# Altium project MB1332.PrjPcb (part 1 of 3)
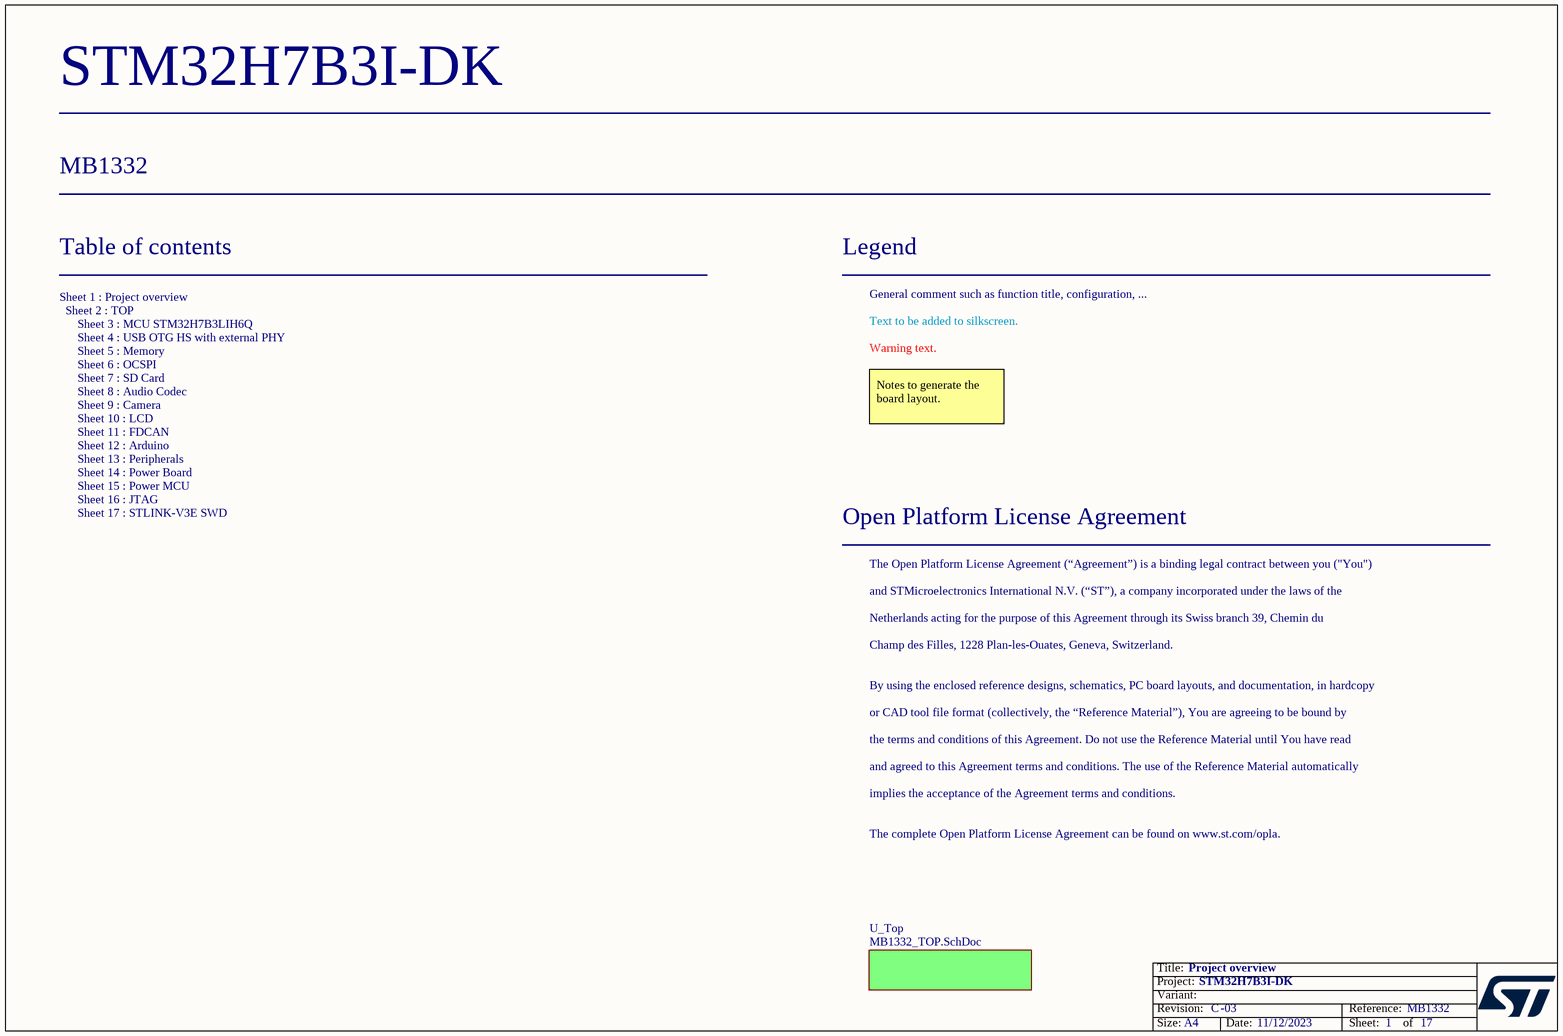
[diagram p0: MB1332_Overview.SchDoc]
Board_Assembly_Revision: 03; Board_Document_Date: 11/12/2023; Board_Name: STM32H7B3I-DK; Board_PCB_Revision: C; Board_Reference: MB1332
17 sheets, 382 parts. Net scope: flat (ports and power ports of the same name join across sheets).
Board file: MB1332.PcbDoc
Sheets:
  MB1332_Overview.SchDoc
    U_Top = MB1332_TOP.SchDoc
      U_Audio_Codec = Audio_Codec.SchDoc
      U_Camera = Camera.SchDoc
      U_FDCAN = FDCAN.SchDoc
      U_LCD = LCD.SchDoc
      U_Memory = Memory.SchDoc
      U_OCSPI = OCSPI.SchDoc
      U_Peripherals = Peripherals.SchDoc
      U_SDcard = SDcard.SchDoc
      U_USB_OTG_HS_externalPHY = USB_OTG_HS_externalPHY.SchDoc
      U_MCU = MCU.SchDoc
      U_Arduino = Arduino.SchDoc
      U_JTAG = JTAG.SchDoc
      U_STLink_V3E_SWD = STLink_V3E_SWD.SchDoc
      U_Power_Board = Power_Board.SchDoc
      U_Power_MCU = Power_MCU.SchDoc

## Sheet MB1332_Overview.SchDoc: Project overview
size A4; Date: Not used; ApprovedBy: Not used; CheckedBy: Not used; Author: Not used; CompanyName: STMicroelectronics; DrawnBy: Not used; Engineer: Not used; Organization: Not used; Address1: Not used; Address2: Not used; Address3: Not used; Address4: Not used; DocumentNumber: Not used; Revision: Not used; SheetNumber: 1; SheetTotal: 17

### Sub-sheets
U_Top = MB1332_TOP.SchDoc: no entries

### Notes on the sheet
- Table of contents
- Legend
- General comment such as function title, configuration, ...
- Text to be added to silkscreen.
- Warning text.
- Notes to generate the board layout.
- Sheet 1 : Project overview
  Sheet 2 : TOP
  Sheet 3 : MCU STM32H7B3LIH6Q
  Sheet 4 : USB OTG HS with external PHY
  Sheet 5 : Memory
  Sheet 6 : OCSPI
  Sheet 7 : SD Card
  Sheet 8 : Audio Codec
  Sheet 9 : Camera
  Sheet 10 : LCD
  Sheet 11 : FDCAN
  Sheet 12 : Arduino
  Sheet 13 : Peripherals
  Sheet 14 : Power Board
  Sheet 15 : Power MCU
  Sheet 16 : JTAG
  Sheet 17 : STLINK-V3E SWD
- Open Platform License Agreement
- The Open Platform License Agreement (“Agreement”) is a binding legal contract between you ("You")
- and STMicroelectronics International N.V. (“ST”), a company incorporated under the laws of the
- Netherlands acting for the purpose of this Agreement through its Swiss branch 39, Chemin du
- Champ des Filles, 1228 Plan-les-Ouates, Geneva, Switzerland.
- By using the enclosed reference designs, schematics, PC board layouts, and documentation, in hardcopy
- or CAD tool file format (collectively, the “Reference Material”), You are agreeing to be bound by
- the terms and conditions of this Agreement. Do not use the Reference Material until You have read
- and agreed to this Agreement terms and conditions. The use of the Reference Material automatically
- implies the acceptance of the Agreement terms and conditions.
- The complete Open Platform License Agreement can be found on www.st.com/opla.

## Sheet MB1332_TOP.SchDoc: TOP
size A3; Date: Not used; ApprovedBy: Not used; CheckedBy: Not used; Author: Not used; CompanyName: STMicroelectronics; DrawnBy: Not used; Engineer: Not used; Organization: Not used; Address1: Not used; Address2: Not used; Address3: Not used; Address4: Not used; DocumentNumber: Not used; Revision: Not used; SheetNumber: 2; SheetTotal: 17
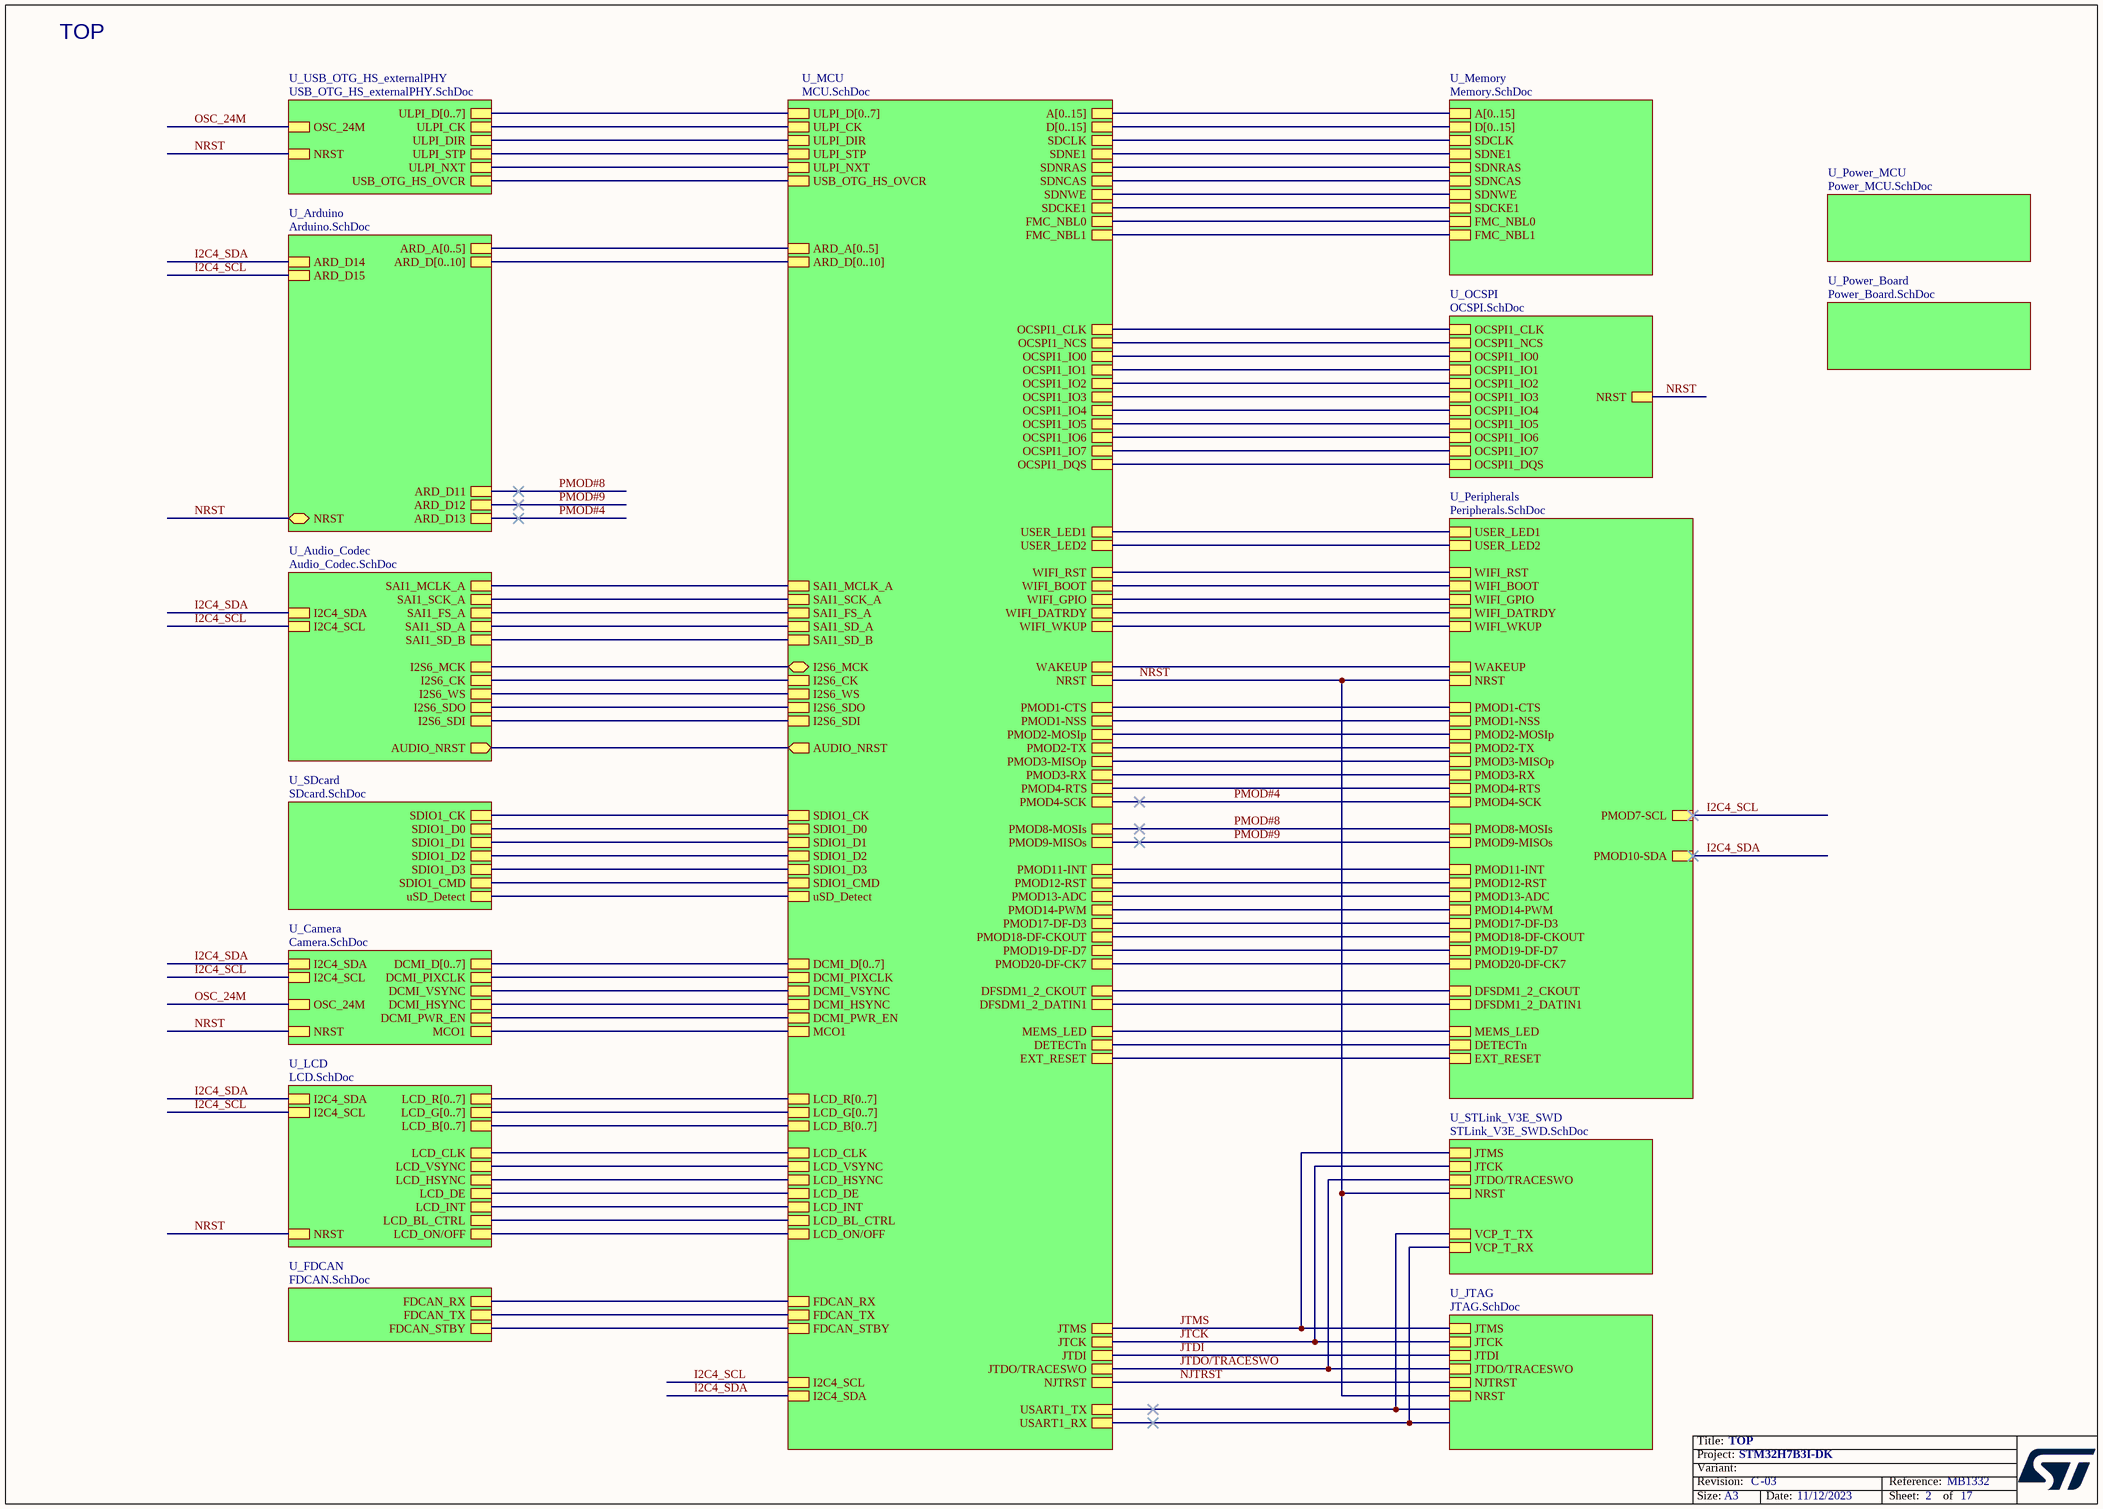
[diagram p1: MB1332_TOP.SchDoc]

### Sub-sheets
U_Arduino = Arduino.SchDoc: ARD_D13, ARD_D12, ARD_D11, ARD_D15, ARD_D14, ARD_A[0..5], ARD_D[0..10], NRST (bidir)
U_Audio_Codec = Audio_Codec.SchDoc: SAI1_MCLK_A, SAI1_SCK_A, SAI1_FS_A, SAI1_SD_A, SAI1_SD_B, I2C4_SCL, I2C4_SDA, I2S6_MCK, I2S6_CK, I2S6_WS, I2S6_SDO, I2S6_SDI, AUDIO_NRST (out)
U_Camera = Camera.SchDoc: NRST, DCMI_D[0..7], DCMI_PWR_EN, DCMI_VSYNC, DCMI_PIXCLK, I2C4_SDA, I2C4_SCL, DCMI_HSYNC, MCO1, OSC_24M
U_FDCAN = FDCAN.SchDoc: FDCAN_STBY, FDCAN_RX, FDCAN_TX
U_JTAG = JTAG.SchDoc: JTMS, JTCK, JTDI, JTDO/TRACESWO, NJTRST, NRST
U_LCD = LCD.SchDoc: LCD_R[0..7], I2C4_SDA, I2C4_SCL, LCD_B[0..7], LCD_G[0..7], NRST, LCD_HSYNC, LCD_VSYNC, LCD_CLK, LCD_DE, LCD_INT, LCD_BL_CTRL, LCD_ON/OFF
U_MCU = MCU.SchDoc: OCSPI1_NCS, SAI1_MCLK_A, SDNCAS, SDNE1, SDCKE1, NRST, LCD_HSYNC, LCD_VSYNC, LCD_CLK, MCO1, OCSPI1_CLK, OCSPI1_DQS, SDIO1_D0, SDIO1_D1, SDIO1_D2, SDIO1_D3, SDIO1_CK, WAKEUP, SDIO1_CMD, FMC_NBL0, FMC_NBL1, SDNRAS, LCD_G[0..7], LCD_B[0..7], D[0..15], A[0..15], ULPI_D[0..7], LCD_R[0..7], LCD_DE, ULPI_STP, ULPI_CK, LCD_INT, uSD_Detect, LCD_BL_CTRL, SAI1_SD_B, SAI1_FS_A, SAI1_SCK_A, SAI1_SD_A, JTMS, JTCK, JTDI, JTDO/TRACESWO, NJTRST, DCMI_HSYNC, DCMI_D[0..7], DCMI_PIXCLK, OCSPI1_IO1, OCSPI1_IO2, OCSPI1_IO3, OCSPI1_IO4, OCSPI1_IO7, OCSPI1_IO6, OCSPI1_IO5, ULPI_DIR, ULPI_NXT, SDNWE, DCMI_VSYNC, DCMI_PWR_EN, I2C4_SDA, I2C4_SCL, I2S6_SDO, I2S6_SDI, I2S6_CK, SDCLK, USB_OTG_HS_OVCR, USART1_TX, USART1_RX, OCSPI1_IO0, LCD_ON/OFF, FDCAN_RX, FDCAN_TX, FDCAN_STBY, MEMS_LED, EXT_RESET, DFSDM1_2_CKOUT, DFSDM1_2_DATIN1, I2S6_WS, WIFI_RST, ARD_A[0..5], ARD_D[0..10], USER_LED2, USER_LED1, AUDIO_NRST (out), PMOD13-ADC, PMOD12-RST, PMOD4-SCK, PMOD20-DF-CK7, PMOD8-MOSIs, PMOD2-MOSIp, PMOD3-RX, PMOD1-NSS, PMOD1-CTS, PMOD2-TX, PMOD11-INT, PMOD4-RTS, PMOD14-PWM, PMOD18-DF-CKOUT, PMOD9-MISOs, PMOD17-DF-D3, PMOD19-DF-D7, PMOD3-MISOp, WIFI_BOOT, I2S6_MCK (bidir), WIFI_WKUP, WIFI_GPIO, WIFI_DATRDY, DETECTn
U_Memory = Memory.SchDoc: FMC_NBL0, FMC_NBL1, D[0..15], A[0..15], SDNCAS, SDNWE, SDNRAS, SDNE1, SDCKE1, SDCLK
U_OCSPI = OCSPI.SchDoc: NRST, OCSPI1_IO0, OCSPI1_IO1, OCSPI1_IO2, OCSPI1_IO3, OCSPI1_IO4, OCSPI1_IO5, OCSPI1_IO6, OCSPI1_IO7, OCSPI1_DQS, OCSPI1_CLK, OCSPI1_NCS
U_Peripherals = Peripherals.SchDoc: WIFI_RST, WAKEUP, NRST, DFSDM1_2_CKOUT, DFSDM1_2_DATIN1, MEMS_LED, EXT_RESET, USER_LED2, USER_LED1, PMOD4-RTS, PMOD2-MOSIp, PMOD3-MISOp, PMOD1-CTS, PMOD2-TX, PMOD8-MOSIs, PMOD9-MISOs, PMOD3-RX, PMOD4-SCK, PMOD7-SCL, PMOD10-SDA, PMOD11-INT, PMOD12-RST, PMOD17-DF-D3, PMOD18-DF-CKOUT, PMOD19-DF-D7, PMOD13-ADC, PMOD14-PWM, PMOD20-DF-CK7, PMOD1-NSS, WIFI_BOOT, WIFI_WKUP, WIFI_GPIO, WIFI_DATRDY, DETECTn
U_Power_Board = Power_Board.SchDoc: no entries
U_Power_MCU = Power_MCU.SchDoc: no entries
U_SDcard = SDcard.SchDoc: SDIO1_D0, SDIO1_D1, SDIO1_D2, SDIO1_D3, SDIO1_CMD, SDIO1_CK, uSD_Detect
U_STLink_V3E_SWD = STLink_V3E_SWD.SchDoc: JTCK, JTDO/TRACESWO, NRST, JTMS, VCP_T_TX, VCP_T_RX
U_USB_OTG_HS_externalPHY = USB_OTG_HS_externalPHY.SchDoc: ULPI_D[0..7], ULPI_CK, ULPI_DIR, ULPI_NXT, ULPI_STP, NRST, USB_OTG_HS_OVCR, OSC_24M

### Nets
I2C4_SCL: sheet U_Audio_Codec/I2C4_SCL, sheet U_Camera/I2C4_SCL, sheet U_LCD/I2C4_SCL, sheet U_Peripherals/PMOD7-SCL, sheet U_MCU/I2C4_SCL, sheet U_Arduino/ARD_D15
I2C4_SDA: sheet U_Audio_Codec/I2C4_SDA, sheet U_Camera/I2C4_SDA, sheet U_LCD/I2C4_SDA, sheet U_Peripherals/PMOD10-SDA, sheet U_MCU/I2C4_SDA, sheet U_Arduino/ARD_D14
JTCK: sheet U_MCU/JTCK, sheet U_JTAG/JTCK, sheet U_STLink_V3E_SWD/JTCK
JTDI: sheet U_MCU/JTDI, sheet U_JTAG/JTDI
JTDO/TRACESWO: sheet U_MCU/JTDO/TRACESWO, sheet U_JTAG/JTDO/TRACESWO, sheet U_STLink_V3E_SWD/JTDO/TRACESWO
JTMS: sheet U_MCU/JTMS, sheet U_JTAG/JTMS, sheet U_STLink_V3E_SWD/JTMS
NJTRST: sheet U_MCU/NJTRST, sheet U_JTAG/NJTRST
NRST: sheet U_Camera/NRST, sheet U_LCD/NRST, sheet U_OCSPI/NRST, sheet U_Peripherals/NRST, sheet U_USB_OTG_HS_externalPHY/NRST, sheet U_MCU/NRST, sheet U_Arduino/NRST, sheet U_JTAG/NRST, sheet U_STLink_V3E_SWD/NRST
OSC_24M: sheet U_Camera/OSC_24M, sheet U_USB_OTG_HS_externalPHY/OSC_24M
PMOD#4: sheet U_Peripherals/PMOD4-SCK, sheet U_MCU/PMOD4-SCK, sheet U_Arduino/ARD_D13
PMOD#8: sheet U_Peripherals/PMOD8-MOSIs, sheet U_MCU/PMOD8-MOSIs, sheet U_Arduino/ARD_D11
PMOD#9: sheet U_Peripherals/PMOD9-MISOs, sheet U_MCU/PMOD9-MISOs, sheet U_Arduino/ARD_D12
(unnamed): sheet U_Audio_Codec/SAI1_MCLK_A, sheet U_MCU/SAI1_MCLK_A
(unnamed): sheet U_Audio_Codec/SAI1_SCK_A, sheet U_MCU/SAI1_SCK_A  [a separate net that carries the same name]
(unnamed): sheet U_Audio_Codec/SAI1_FS_A, sheet U_MCU/SAI1_FS_A  [a separate net that carries the same name]
(unnamed): sheet U_Audio_Codec/SAI1_SD_A, sheet U_MCU/SAI1_SD_A  [a separate net that carries the same name]
(unnamed): sheet U_Audio_Codec/SAI1_SD_B, sheet U_MCU/SAI1_SD_B  [a separate net that carries the same name]
(unnamed): sheet U_Audio_Codec/I2S6_MCK, sheet U_MCU/I2S6_MCK  [a separate net that carries the same name]
(unnamed): sheet U_Audio_Codec/I2S6_CK, sheet U_MCU/I2S6_CK  [a separate net that carries the same name]
(unnamed): sheet U_Audio_Codec/I2S6_WS, sheet U_MCU/I2S6_WS  [a separate net that carries the same name]
(unnamed): sheet U_Audio_Codec/I2S6_SDO, sheet U_MCU/I2S6_SDO  [a separate net that carries the same name]
(unnamed): sheet U_Audio_Codec/I2S6_SDI, sheet U_MCU/I2S6_SDI  [a separate net that carries the same name]
(unnamed): sheet U_Audio_Codec/AUDIO_NRST, sheet U_MCU/AUDIO_NRST  [a separate net that carries the same name]
(unnamed): sheet U_Camera/DCMI_PWR_EN, sheet U_MCU/DCMI_PWR_EN  [a separate net that carries the same name]
(unnamed): sheet U_Camera/DCMI_VSYNC, sheet U_MCU/DCMI_VSYNC  [a separate net that carries the same name]
(unnamed): sheet U_Camera/DCMI_PIXCLK, sheet U_MCU/DCMI_PIXCLK  [a separate net that carries the same name]
(unnamed): sheet U_Camera/DCMI_HSYNC, sheet U_MCU/DCMI_HSYNC  [a separate net that carries the same name]
(unnamed): sheet U_Camera/MCO1, sheet U_MCU/MCO1  [a separate net that carries the same name]
(unnamed): sheet U_FDCAN/FDCAN_STBY, sheet U_MCU/FDCAN_STBY  [a separate net that carries the same name]
(unnamed): sheet U_FDCAN/FDCAN_RX, sheet U_MCU/FDCAN_RX  [a separate net that carries the same name]
(unnamed): sheet U_FDCAN/FDCAN_TX, sheet U_MCU/FDCAN_TX  [a separate net that carries the same name]
(unnamed): sheet U_LCD/LCD_HSYNC, sheet U_MCU/LCD_HSYNC  [a separate net that carries the same name]
(unnamed): sheet U_LCD/LCD_VSYNC, sheet U_MCU/LCD_VSYNC  [a separate net that carries the same name]
(unnamed): sheet U_LCD/LCD_CLK, sheet U_MCU/LCD_CLK  [a separate net that carries the same name]
(unnamed): sheet U_LCD/LCD_DE, sheet U_MCU/LCD_DE  [a separate net that carries the same name]
(unnamed): sheet U_LCD/LCD_INT, sheet U_MCU/LCD_INT  [a separate net that carries the same name]
(unnamed): sheet U_LCD/LCD_BL_CTRL, sheet U_MCU/LCD_BL_CTRL  [a separate net that carries the same name]
(unnamed): sheet U_LCD/LCD_ON/OFF, sheet U_MCU/LCD_ON/OFF  [a separate net that carries the same name]
(unnamed): sheet U_Memory/FMC_NBL0, sheet U_MCU/FMC_NBL0  [a separate net that carries the same name]
(unnamed): sheet U_Memory/FMC_NBL1, sheet U_MCU/FMC_NBL1  [a separate net that carries the same name]
(unnamed): sheet U_Memory/SDNCAS, sheet U_MCU/SDNCAS  [a separate net that carries the same name]
(unnamed): sheet U_Memory/SDNWE, sheet U_MCU/SDNWE  [a separate net that carries the same name]
(unnamed): sheet U_Memory/SDNRAS, sheet U_MCU/SDNRAS  [a separate net that carries the same name]
(unnamed): sheet U_Memory/SDNE1, sheet U_MCU/SDNE1  [a separate net that carries the same name]
(unnamed): sheet U_Memory/SDCKE1, sheet U_MCU/SDCKE1  [a separate net that carries the same name]
(unnamed): sheet U_Memory/SDCLK, sheet U_MCU/SDCLK  [a separate net that carries the same name]
(unnamed): sheet U_OCSPI/OCSPI1_IO0, sheet U_MCU/OCSPI1_IO0  [a separate net that carries the same name]
(unnamed): sheet U_OCSPI/OCSPI1_IO1, sheet U_MCU/OCSPI1_IO1  [a separate net that carries the same name]
(unnamed): sheet U_OCSPI/OCSPI1_IO2, sheet U_MCU/OCSPI1_IO2  [a separate net that carries the same name]
(unnamed): sheet U_OCSPI/OCSPI1_IO3, sheet U_MCU/OCSPI1_IO3  [a separate net that carries the same name]
(unnamed): sheet U_OCSPI/OCSPI1_IO4, sheet U_MCU/OCSPI1_IO4  [a separate net that carries the same name]
(unnamed): sheet U_OCSPI/OCSPI1_IO5, sheet U_MCU/OCSPI1_IO5  [a separate net that carries the same name]
(unnamed): sheet U_OCSPI/OCSPI1_IO6, sheet U_MCU/OCSPI1_IO6  [a separate net that carries the same name]
(unnamed): sheet U_OCSPI/OCSPI1_IO7, sheet U_MCU/OCSPI1_IO7  [a separate net that carries the same name]
(unnamed): sheet U_OCSPI/OCSPI1_DQS, sheet U_MCU/OCSPI1_DQS  [a separate net that carries the same name]
(unnamed): sheet U_OCSPI/OCSPI1_CLK, sheet U_MCU/OCSPI1_CLK  [a separate net that carries the same name]
(unnamed): sheet U_OCSPI/OCSPI1_NCS, sheet U_MCU/OCSPI1_NCS  [a separate net that carries the same name]
(unnamed): sheet U_Peripherals/WIFI_RST, sheet U_MCU/WIFI_RST  [a separate net that carries the same name]
(unnamed): sheet U_Peripherals/WAKEUP, sheet U_MCU/WAKEUP  [a separate net that carries the same name]
(unnamed): sheet U_Peripherals/DFSDM1_2_CKOUT, sheet U_MCU/DFSDM1_2_CKOUT  [a separate net that carries the same name]
(unnamed): sheet U_Peripherals/DFSDM1_2_DATIN1, sheet U_MCU/DFSDM1_2_DATIN1  [a separate net that carries the same name]
(unnamed): sheet U_Peripherals/MEMS_LED, sheet U_MCU/MEMS_LED  [a separate net that carries the same name]
(unnamed): sheet U_Peripherals/EXT_RESET, sheet U_MCU/EXT_RESET  [a separate net that carries the same name]
(unnamed): sheet U_Peripherals/USER_LED2, sheet U_MCU/USER_LED2  [a separate net that carries the same name]
(unnamed): sheet U_Peripherals/USER_LED1, sheet U_MCU/USER_LED1  [a separate net that carries the same name]
(unnamed): sheet U_Peripherals/PMOD4-RTS, sheet U_MCU/PMOD4-RTS  [a separate net that carries the same name]
(unnamed): sheet U_Peripherals/PMOD2-MOSIp, sheet U_MCU/PMOD2-MOSIp  [a separate net that carries the same name]
(unnamed): sheet U_Peripherals/PMOD3-MISOp, sheet U_MCU/PMOD3-MISOp  [a separate net that carries the same name]
(unnamed): sheet U_Peripherals/PMOD1-CTS, sheet U_MCU/PMOD1-CTS  [a separate net that carries the same name]
(unnamed): sheet U_Peripherals/PMOD2-TX, sheet U_MCU/PMOD2-TX  [a separate net that carries the same name]
(unnamed): sheet U_Peripherals/PMOD3-RX, sheet U_MCU/PMOD3-RX  [a separate net that carries the same name]
(unnamed): sheet U_Peripherals/PMOD11-INT, sheet U_MCU/PMOD11-INT  [a separate net that carries the same name]
(unnamed): sheet U_Peripherals/PMOD12-RST, sheet U_MCU/PMOD12-RST  [a separate net that carries the same name]
(unnamed): sheet U_Peripherals/PMOD17-DF-D3, sheet U_MCU/PMOD17-DF-D3  [a separate net that carries the same name]
(unnamed): sheet U_Peripherals/PMOD18-DF-CKOUT, sheet U_MCU/PMOD18-DF-CKOUT  [a separate net that carries the same name]
(unnamed): sheet U_Peripherals/PMOD19-DF-D7, sheet U_MCU/PMOD19-DF-D7  [a separate net that carries the same name]
(unnamed): sheet U_Peripherals/PMOD13-ADC, sheet U_MCU/PMOD13-ADC  [a separate net that carries the same name]
(unnamed): sheet U_Peripherals/PMOD14-PWM, sheet U_MCU/PMOD14-PWM  [a separate net that carries the same name]
(unnamed): sheet U_Peripherals/PMOD20-DF-CK7, sheet U_MCU/PMOD20-DF-CK7  [a separate net that carries the same name]
(unnamed): sheet U_Peripherals/PMOD1-NSS, sheet U_MCU/PMOD1-NSS  [a separate net that carries the same name]
(unnamed): sheet U_Peripherals/WIFI_BOOT, sheet U_MCU/WIFI_BOOT  [a separate net that carries the same name]
(unnamed): sheet U_Peripherals/WIFI_WKUP, sheet U_MCU/WIFI_WKUP  [a separate net that carries the same name]
(unnamed): sheet U_Peripherals/WIFI_GPIO, sheet U_MCU/WIFI_GPIO  [a separate net that carries the same name]
(unnamed): sheet U_Peripherals/WIFI_DATRDY, sheet U_MCU/WIFI_DATRDY  [a separate net that carries the same name]
(unnamed): sheet U_Peripherals/DETECTn, sheet U_MCU/DETECTn  [a separate net that carries the same name]
(unnamed): sheet U_SDcard/SDIO1_D0, sheet U_MCU/SDIO1_D0  [a separate net that carries the same name]
(unnamed): sheet U_SDcard/SDIO1_D1, sheet U_MCU/SDIO1_D1  [a separate net that carries the same name]
(unnamed): sheet U_SDcard/SDIO1_D2, sheet U_MCU/SDIO1_D2  [a separate net that carries the same name]
(unnamed): sheet U_SDcard/SDIO1_D3, sheet U_MCU/SDIO1_D3  [a separate net that carries the same name]
(unnamed): sheet U_SDcard/SDIO1_CMD, sheet U_MCU/SDIO1_CMD  [a separate net that carries the same name]
(unnamed): sheet U_SDcard/SDIO1_CK, sheet U_MCU/SDIO1_CK  [a separate net that carries the same name]
(unnamed): sheet U_SDcard/uSD_Detect, sheet U_MCU/uSD_Detect  [a separate net that carries the same name]
(unnamed): sheet U_USB_OTG_HS_externalPHY/ULPI_CK, sheet U_MCU/ULPI_CK  [a separate net that carries the same name]
(unnamed): sheet U_USB_OTG_HS_externalPHY/ULPI_DIR, sheet U_MCU/ULPI_DIR  [a separate net that carries the same name]
(unnamed): sheet U_USB_OTG_HS_externalPHY/ULPI_NXT, sheet U_MCU/ULPI_NXT  [a separate net that carries the same name]
(unnamed): sheet U_USB_OTG_HS_externalPHY/ULPI_STP, sheet U_MCU/ULPI_STP  [a separate net that carries the same name]
(unnamed): sheet U_USB_OTG_HS_externalPHY/USB_OTG_HS_OVCR, sheet U_MCU/USB_OTG_HS_OVCR  [a separate net that carries the same name]
(unnamed): sheet U_MCU/USART1_TX, sheet U_STLink_V3E_SWD/VCP_T_TX  [a separate net that carries the same name]
(unnamed): sheet U_MCU/USART1_RX, sheet U_STLink_V3E_SWD/VCP_T_RX  [a separate net that carries the same name]

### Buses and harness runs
bus sheet U_Arduino/ARD_A[0..5] = sheet U_MCU/ARD_A[0..5]
bus sheet U_Arduino/ARD_D[0..10] = sheet U_MCU/ARD_D[0..10]
bus sheet U_Camera/DCMI_D[0..7] = sheet U_MCU/DCMI_D[0..7]
bus sheet U_LCD/LCD_B[0..7] = sheet U_MCU/LCD_B[0..7]
bus sheet U_LCD/LCD_G[0..7] = sheet U_MCU/LCD_G[0..7]
bus sheet U_LCD/LCD_R[0..7] = sheet U_MCU/LCD_R[0..7]
bus sheet U_MCU/A[0..15] = sheet U_Memory/A[0..15]
bus sheet U_MCU/D[0..15] = sheet U_Memory/D[0..15]
bus sheet U_MCU/ULPI_D[0..7] = sheet U_USB_OTG_HS_externalPHY/ULPI_D[0..7]

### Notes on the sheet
- TOP

## Sheet Audio_Codec.SchDoc: Audio Codec
size A4; Date: Not used; ApprovedBy: Not used; CheckedBy: Not used; Author: Not used; CompanyName: STMicroelectronics; DrawnBy: Not used; Engineer: Not used; Organization: Not used; Address1: Not used; Address2: Not used; Address3: Not used; Address4: Not used; DocumentNumber: Not used; Revision: Not used; SheetNumber: 8; SheetTotal: 17
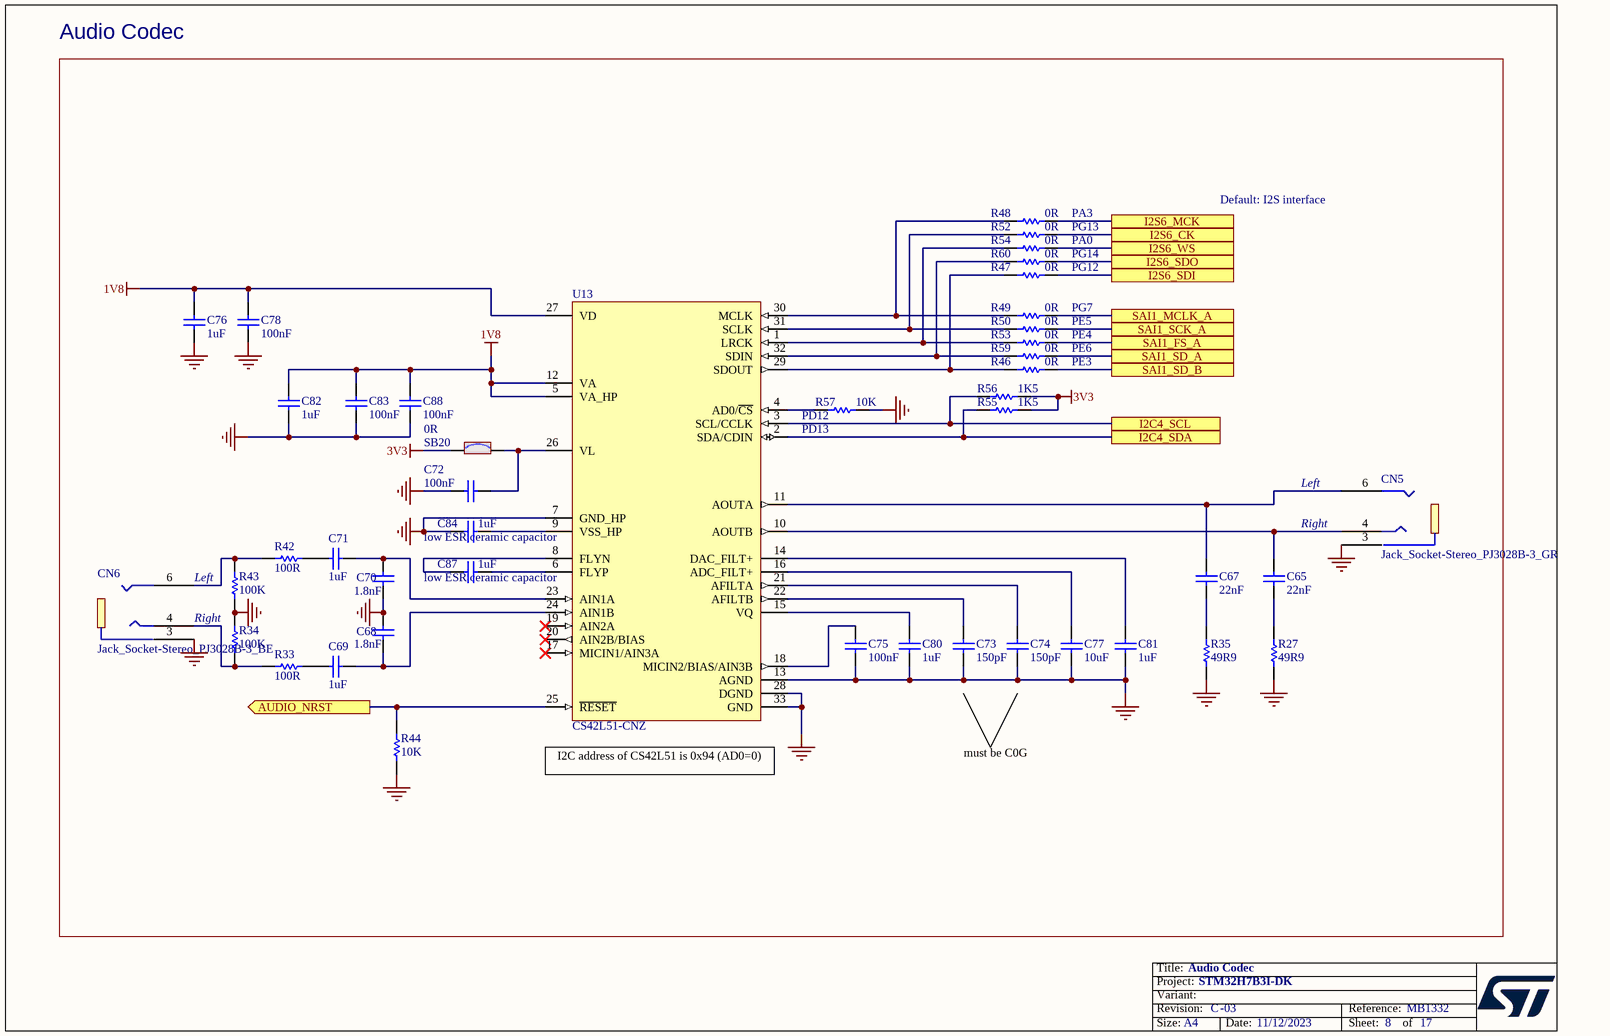
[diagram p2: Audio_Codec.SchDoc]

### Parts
C65  value 22nF  [C0603]  (hidden comment: Capacitor)
C67  value 22nF  [C0603]  (hidden comment: Capacitor)
C68  value 1.8nF  [C0402]  (hidden comment: Capacitor)
C69  value 1uF  [C0402]  (hidden comment: Capacitor)
C70  value 1.8nF  [C0402]  (hidden comment: Capacitor)
C71  value 1uF  [C0402]  (hidden comment: Capacitor)
C72  value 100nF  [C0402]  (hidden comment: Capacitor)
C73  value 150pF  [C0402]  (hidden comment: Capacitor)
C74  value 150pF  [C0402]  (hidden comment: Capacitor)
C75  value 100nF  [C0402]  (hidden comment: Capacitor)
C76  value 1uF  [C0402]  (hidden comment: Capacitor)
C77  value 10uF  [C0603]  (hidden comment: Capacitor)
C78  value 100nF  [C0402]  (hidden comment: Capacitor)
C80  value 1uF  [C0402]  (hidden comment: Capacitor)
C81  value 1uF  [C0402]  (hidden comment: Capacitor)
C82  value 1uF  [C0402]  (hidden comment: Capacitor)
C83  value 100nF  [C0402]  (hidden comment: Capacitor)
C84  value 1uF  [C0402]  (hidden comment: Capacitor)
C87  value 1uF  [C0402]  (hidden comment: Capacitor)
C88  value 100nF  [C0402]  (hidden comment: Capacitor)
CN5  value Jack_Socket-Stereo_PJ3028B-3_GR  [CON_PHONE-JACK-3P5_HY_PJ3028B]  (hidden comment: Jack_PJ3028B-3_3P)
CN6  value Jack_Socket-Stereo_PJ3028B-3_BE  [CON_PHONE-JACK-3P5_HY_PJ3028B]  (hidden comment: Jack_PJ3028B-3_3P)
R27  value 49R9  [R0603]  (hidden comment: Resistor)
R33  value 100R  [R0402]  (hidden comment: Resistor)
R34  value 100K  [R0402]  (hidden comment: Resistor)
R35  value 49R9  [R0603]  (hidden comment: Resistor)
R42  value 100R  [R0402]  (hidden comment: Resistor)
R43  value 100K  [R0402]  (hidden comment: Resistor)
R44  value 10K  [R0402]  (hidden comment: Resistor)
R46  value 0R  [R0402]  (hidden comment: Resistor)
R47  value 0R  [R0402]  (hidden comment: Resistor)
R48  value 0R  [R0402]  (hidden comment: Resistor)
R49  value 0R  [R0402]  (hidden comment: Resistor)
R50  value 0R  [R0402]  (hidden comment: Resistor)
R52  value 0R  [R0402]  (hidden comment: Resistor)
R53  value 0R  [R0402]  (hidden comment: Resistor)
R54  value 0R  [R0402]  (hidden comment: Resistor)
R55  value 1K5  [R0402]  (hidden comment: Resistor)
R56  value 1K5  [R0402]  (hidden comment: Resistor)
R57  value 10K  [R0402]  (hidden comment: Resistor)
R59  value 0R  [R0402]  (hidden comment: Resistor)
R60  value 0R  [R0402]  (hidden comment: Resistor)
SB20  value 0R  [SOLDER-BRIDGE_R0603-0R]  (hidden comment: SB_ON)
U13  CS42L51-CNZ  [ICC_QFN32-EPAD_5X5_P050]

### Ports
AUDIO_NRST (out), I2C4_SCL, I2C4_SDA, I2S6_CK, I2S6_MCK, I2S6_SDI, I2S6_SDO, I2S6_WS, SAI1_FS_A, SAI1_MCLK_A, SAI1_SCK_A, SAI1_SD_A, SAI1_SD_B

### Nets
1V8: C76.2 C78.2 C82.1 C83.2 C88.2 U13.5(VA_HP) U13.12(VA) U13.27(VD)
3V3: R55.2 R56.2 SB20.1
GND: C68.2 C70.1 C72.2 C73.1 C74.1 C75.2 C76.1 C77.1 C78.1 C80.2 C81.2 C82.2 C83.1 C84.2 C88.1 CN5.3 CN6.3 R27.1 R34.2 R35.1 R43.1 R44.1 R57.2 U13.7(GND_HP) U13.13(AGND) U13.28(DGND) U13.33(GND)
AUDIO_NRST: R44.2 U13.25(~{RESET}) ; port AUDIO_NRST
I2C4_SCL: R56.1 U13.3(SCL/CCLK) ; port I2C4_SCL
I2C4_SDA: R55.1 U13.2(SDA/CDIN) ; port I2C4_SDA
I2S6_CK: R52.2 ; port I2S6_CK
I2S6_MCK: R48.2 ; port I2S6_MCK
I2S6_SDI: R47.2 ; port I2S6_SDI
I2S6_SDO: R60.2 ; port I2S6_SDO
I2S6_WS: R54.2 ; port I2S6_WS
SAI1_FS_A: R53.2 ; port SAI1_FS_A
SAI1_MCLK_A: R49.2 ; port SAI1_MCLK_A
SAI1_SCK_A: R50.2 ; port SAI1_SCK_A
SAI1_SD_A: R59.2 ; port SAI1_SD_A
SAI1_SD_B: R46.2 ; port SAI1_SD_B
NetC65_1: C65.1 CN5.4 U13.10(AOUTB)
NetC65_2: C65.2 R27.2
NetC67_1: C67.1 R35.2
NetC67_2: C67.2 CN5.6 U13.11(AOUTA)
NetC68_1: C68.1 C69.2 U13.24(AIN1B)
NetC69_1: C69.1 R33.2
NetC70_2: C70.2 C71.2 U13.23(AIN1A)
NetC71_1: C71.1 R42.2
NetC72_1: C72.1 SB20.2 U13.26(VL)
NetC73_2: C73.2 U13.22(AFILTB)
NetC74_2: C74.2 U13.21(AFILTA)
NetC75_1: C75.1 U13.18(MICIN2/BIAS/AIN3B)
NetC77_2: C77.2 U13.16(ADC_FILT+)
NetC80_1: C80.1 U13.15(VQ)
NetC81_1: C81.1 U13.14(DAC_FILT+)
NetC84_1: C84.1 U13.9(VSS_HP)
NetC87_1: C87.1 U13.6(FLYP)
NetC87_2: C87.2 U13.8(FLYN)
NetCN6_4: CN6.4 R33.1 R34.1
NetCN6_6: CN6.6 R42.1 R43.2
NetR46_1: R46.1 R47.1 U13.29(SDOUT)
NetR48_1: R48.1 R49.1 U13.30(MCLK)
NetR50_1: R50.1 R52.1 U13.31(SCLK)
NetR53_1: R53.1 R54.1 U13.1(LRCK)
NetR57_1: R57.1 U13.4(AD0/~{CS})
NetR59_1: R59.1 R60.1 U13.32(SDIN)

Not connected (* = marked no-connect by the designer): U13 17(MICIN1/AIN3A)* 19(AIN2A)* 20(AIN2B/BIAS)*

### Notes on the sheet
- Audio Codec
- PA0
- PA3
- PG13
- Default: I2S interface
- PG7
- PG14
- PG12
- PE5
- PE4
- PE6
- PE3
- (near R57) PD12
- (near R57) PD13
- Left
- (near R43) Left
- low ESR ceramic capacitor
- Right
- (near U13) I2C address of CS42L51 is 0x94 (AD0=0)
- must be C0G

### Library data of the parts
C65 C67 = MCD-00555: Capacitor, MLCC, 22nF, 10%, 25V, X7R, 0603, T=0,8mm; Manufacturer_Part_Number: CC0603KRX7R8BB223; Manufacturer: YAGEO; Part_Preference: Recommended; Provided_By: SUBCO; Component_Country_Of_Origin: China; ID: 3190; ShowFields: YES
C68 C70 = MCD-00694: Capacitor, MLCC, 1.8nF, 50V, X7R, 10%, 0402, T=0.5mm; Manufacturer_Part_Number: CC0402KRX7R9BB182; Manufacturer: YAGEO; Part_Preference: Recommended; Provided_By: SUBCO; Component_Country_Of_Origin: China; ID: 3045; ShowFields: YES
C69 C71 C76 C80-C82 C84 C87 = MCD-01722: Capacitor, 1uF, 10V, X5R, 10%, 0402, T=0.5mm; Manufacturer_Part_Number: CC0402KRX5R6BB105; Manufacturer: YAGEO; Part_Preference: Recommended; Provided_By: SUBCO; Component_Country_Of_Origin: China; ID: 3822; ShowFields: YES
C72 C75 C78 C83 C88 = MCD-00006: Capacitor, MLCC, 100nF, 16V, X7R, +/-10%, 0402, T=0.5mm; Manufacturer_Part_Number: CC0402KRX7R7BB104; Manufacturer: YAGEO; Part_Preference: Recommended; Partial_Alternate_Internal_Part_Number: MCD-03299; Order_Code_RS: 9402047; Component_Country_Of_Origin: China; ShowFields: YES; ID: 2474
C73 C74 = MCD-00672: Capacitor, MLCC, 150pF, 50V, NPO, 5%, 0402, T=0,5mm; Manufacturer_Part_Number: CC0402JRNPO9BN151; Manufacturer: YAGEO; Part_Preference: Recommended; Provided_By: SUBCO; Component_Country_Of_Origin: China; ID: 3069; ShowFields: YES
C77 = MCD-00098: Capacitor, MLCC, 10uF, 6V3, X5R, 10%, 0603, T=0,8mm; Manufacturer_Part_Number: CC0603KRX5R5BB106; Manufacturer: YAGEO; Part_Preference: Recommended; Provided_By: SUBCO; Component_Country_Of_Origin: China; ID: 2773; ShowFields: YES
CN5 = MCD-00018: Connector Jack socket Stereo 3.5mm, 3 pins, RA, SMT, Green (Line output); Manufacturer_Part_Number: PJ3028B-3_GR; Manufacturer: QIAOD; Alternate_Manufacturer_Part_Number: PJ30280-3_GR; Part_Preference: Recommended; Provided_By: SUBCO; Component_Country_Of_Origin: Unknown; ID: 2498; ShowFields: YES
CN6 = MCD-00682: Connector Jack socket Stereo 3.5mm, 3 pins, RA, SMT, Blue (Line input); Manufacturer_Part_Number: PJ3028B-3_BE; Manufacturer: QIAOD; Alternate_Manufacturer_Part_Number: PJ30280-3_BE; Part_Preference: Recommended; Provided_By: SUBCO; Component_Country_Of_Origin: Unknown; ID: 3061; ShowFields: YES
R27 R35 = MCD-00564: Resistor,49R9,0603,1%,1/10W; Manufacturer_Part_Number: RC0603FR-0749R9L; Manufacturer: YAGEO; Part_Preference: Recommended; Provided_By: SUBCO; Component_Country_Of_Origin: China; ID: 3180; ShowFields: YES
R33 R42 = MCD-00067: Resistor, 100R, 0402, +/- 1%, 1/16W; Manufacturer_Part_Number: RC0402FR-07100RL; Manufacturer: YAGEO; Part_Preference: Recommended; Order_Code_RS: 9239111; Component_Country_Of_Origin: China; ShowFields: YES; ID: 2527
R34 R43 = MCD-00059: Resistor,100K,0402,1%,1/16W; Manufacturer_Part_Number: RC0402FR-07100KL; Manufacturer: YAGEO; Alternate_Manufacturer_Part_Number: RT0402FRE07100KL; Part_Preference: Recommended; Partial_Alternate_Internal_Part_Number: MCD-03301; Provided_By: SUBCO; Component_Country_Of_Origin: China; ID: 2533; Order_Code_RS: 2421891; ShowFields: YES
R44 R57 = MCD-00053: Resistor,10K,0402,1%,1/16W; Manufacturer_Part_Number: RC0402FR-0710KL; Manufacturer: YAGEO; BMS_Part_Number: 9131590; Part_Preference: Recommended; Provided_By: SUBCO; Component_Country_Of_Origin: China; ID: 2539; Order_Code_RS: 9239359; ShowFields: YES
R46-R50 R52-R54 R59 R60 = MCD-00052: Resistor,0R,0402,5%,1/16W; Manufacturer_Part_Number: RC0402JR-070RL; Manufacturer: YAGEO; Part_Preference: Recommended; Provided_By: SUBCO; Component_Country_Of_Origin: China; ID: 2540; Order_Code_RS: 9232516RL; ShowFields: YES
R55 R56 = MCD-00068: Resistor,1K5,0402,1%,1/16W; Manufacturer_Part_Number: RC0402FR-071K5L; Manufacturer: YAGEO; Part_Preference: Recommended; Provided_By: SUBCO; Component_Country_Of_Origin: China; ID: 2524; Order_Code_RS: 9239251; ShowFields: YES
SB20 = MCD-00071: Solder Bridge ON; Part_Type: Resistor; Manufacturer_Part_Number: RC0603JR-070RL; Manufacturer: YAGEO; Manufacturer_HQ_COO: Unknown; Part_Preference: Recommended; Provided_By: SUBCO; Component_Country_Of_Origin: China; ID: 2521; Order_Code_RS: 199-5647; ShowFields: YES
U13 = MCD-00265: Low-Power, Stereo Codec with Headphone Amp; Part_Type: IC; Manufacturer: CIRRUS LOGIC; Part_Preference: Forbidden; Provided_By: SUBCO; Component_Country_Of_Origin: China; ID: 2602; ShowFields: YES

## Sheet Camera.SchDoc: Camera
size A4; Date: Not used; ApprovedBy: Not used; CheckedBy: Not used; Author: Not used; CompanyName: STMicroelectronics; DrawnBy: Not used; Engineer: Not used; Organization: Not used; Address1: Not used; Address2: Not used; Address3: Not used; Address4: Not used; DocumentNumber: Not used; Revision: Not used; SheetNumber: 9; SheetTotal: 17
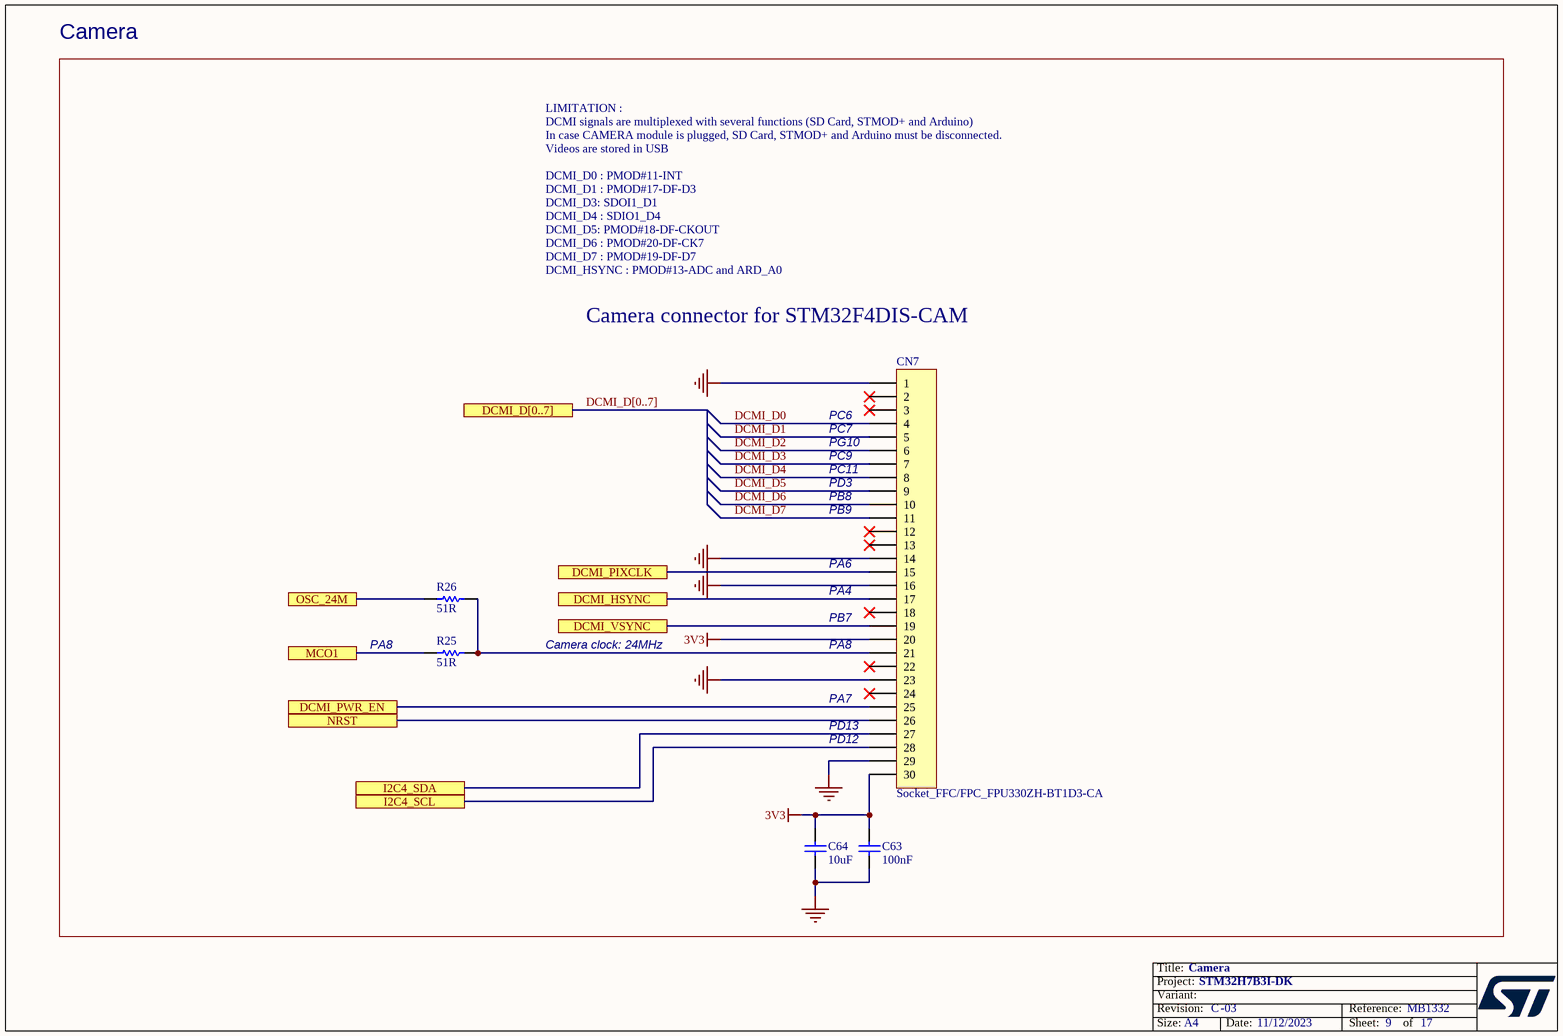
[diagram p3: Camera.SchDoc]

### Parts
C63  value 100nF  [C0402]  (hidden comment: Capacitor)
C64  value 10uF  [C0603]  (hidden comment: Capacitor)
CN7  value Socket_FFC/FPC_FPU330ZH-BT1D3-CA  [CON_TOWNES_FPU330ZH-BT1D3-CA_P050]  (hidden comment: FPU330ZH-BT1D3-CA)
R25  value 51R  [R0402]  (hidden comment: Resistor)
R26  value 51R  [R0402]  (hidden comment: Resistor)

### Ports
DCMI_D[0..7], DCMI_HSYNC, DCMI_PIXCLK, DCMI_PWR_EN, DCMI_VSYNC, I2C4_SCL, I2C4_SDA, MCO1, NRST, OSC_24M

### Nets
3V3: C63.2 C64.2 CN7.20 CN7.30
GND: C63.1 C64.1 CN7.1 CN7.14 CN7.16 CN7.23 CN7.29
DCMI_D0: CN7.4
DCMI_D1: CN7.5
DCMI_D2: CN7.6
DCMI_D3: CN7.7
DCMI_D4: CN7.8
DCMI_D5: CN7.9
DCMI_D6: CN7.10
DCMI_D7: CN7.11
DCMI_HSYNC: CN7.17 ; port DCMI_HSYNC
DCMI_PIXCLK: CN7.15 ; port DCMI_PIXCLK
DCMI_PWR_EN: CN7.25 ; port DCMI_PWR_EN
DCMI_VSYNC: CN7.19 ; port DCMI_VSYNC
I2C4_SCL: CN7.28 ; port I2C4_SCL
I2C4_SDA: CN7.27 ; port I2C4_SDA
MCO1: R25.1 ; port MCO1
OSC_24M: R26.1 ; port OSC_24M
T_NRST: CN7.26 ; port NRST
NetCN7_21: CN7.21 R25.2 R26.2

Not connected (* = marked no-connect by the designer): CN7 2* 3* 12* 13* 18* 22* 24*

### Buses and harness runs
bus DCMI_D[0..7] = port DCMI_D[0..7]

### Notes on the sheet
- Camera
- LIMITATION :
  DCMI signals are multiplexed with several functions (SD Card, STMOD+ and Arduino)
  In case CAMERA module is plugged, SD Card, STMOD+ and Arduino must be disconnected.
  Videos are stored in USB
  DCMI_D0 : PMOD#11-INT
  DCMI_D1 : PMOD#17-DF-D3
  DCMI_D3: SDOI1_D1
  DCMI_D4 : SDIO1_D4
  DCMI_D5: PMOD#18-DF-CKOUT
  DCMI_D6 : PMOD#20-DF-CK7
  DCMI_D7 : PMOD#19-DF-D7
  DCMI_HSYNC : PMOD#13-ADC and ARD_A0
- Camera connector for STM32F4DIS-CAM
- (near CN7) PC7
- (near CN7) PG10
- (near CN7) PC6
- (near CN7) PB8
- (near CN7) PC9
- (near CN7) PC11
- (near CN7) PD3
- (near CN7) PB9
- (near CN7) PA6
- PA8
- Camera clock: 24MHz
- (near CN7) PA4
- (near CN7) PB7
- (near CN7) PA8
- (near CN7) PA7
- (near CN7) PD12
- (near CN7) PD13

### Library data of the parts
C63 = MCD-00006: as C72 on sheet Audio_Codec
C64 = MCD-00098: as C77 on sheet Audio_Codec
CN7 = MCD-00326: Connector FFC/FPC ZIF 0.5mm 30 pins, Lower Contacts; Manufacturer: TOWNES; Part_Preference: Recommended; Provided_By: SUBCO; Component_Country_Of_Origin: Unknown; ID: 2956; ShowFields: YES
R25 R26 = MCD-00485: Resistor,51R,0402,1%,1/16W; Manufacturer_Part_Number: RC0402FR-0751RL; Manufacturer: YAGEO; Part_Preference: Recommended; Provided_By: SUBCO; Component_Country_Of_Origin: China; ID: 2790; ShowFields: YES

## Sheet FDCAN.SchDoc: FDCAN
size A4; Date: Not used; ApprovedBy: Not used; CheckedBy: Not used; Author: Not used; CompanyName: STMicroelectronics; DrawnBy: Not used; Engineer: Not used; Organization: Not used; Address1: Not used; Address2: Not used; Address3: Not used; Address4: Not used; DocumentNumber: Not used; Revision: Not used; SheetNumber: 11; SheetTotal: 17
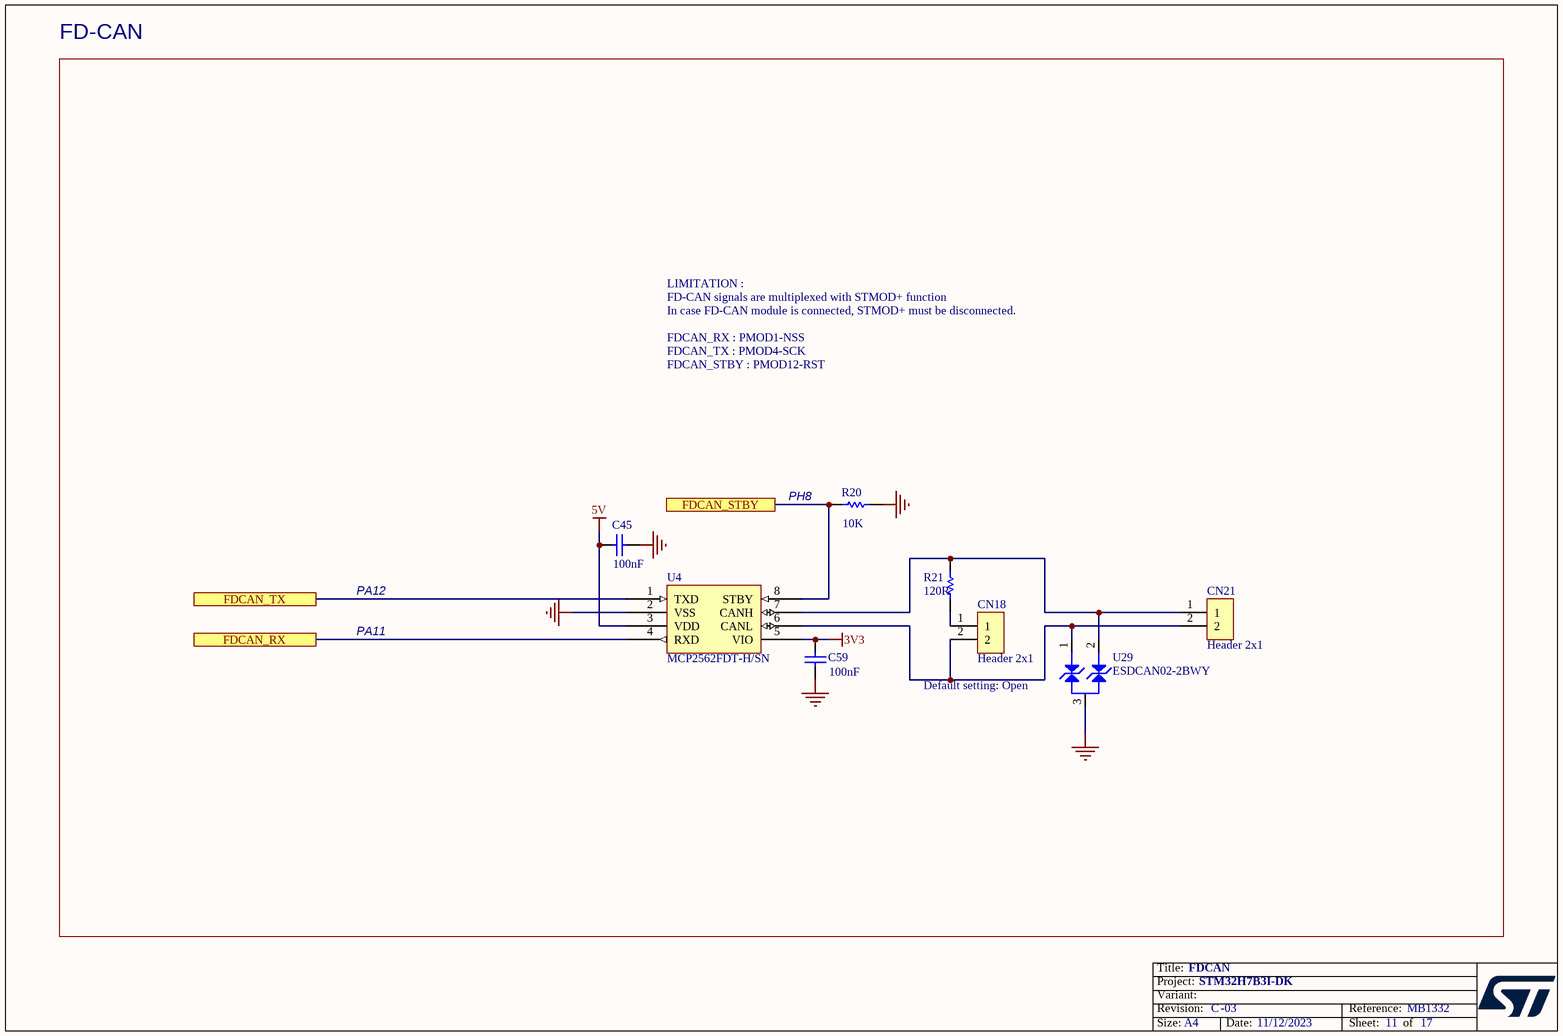
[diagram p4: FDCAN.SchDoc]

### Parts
C45  value 100nF  [C0402]  (hidden comment: Capacitor)
C59  value 100nF  [C0402]  (hidden comment: Capacitor)
CN18  Header 2x1  [CON_SAMTEC_TSW-102-07-G-S]
CN21  Header 2x1  [CON_SAMTEC_TSW-102-07-G-S]
R20  value 10K  [R0402]  (hidden comment: Resistor)
R21  value 120R  [R0402]  (hidden comment: Resistor)
U4  value MCP2562FDT-H/SN  [ICC_SO8_5X4_P127]  (hidden comment: MCP2562FD)
U29  value ESDCAN02-2BWY  [DIO_SOT323]  (hidden comment: ESD-TRANSIL-DUAL-BIDIR)

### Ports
FDCAN_RX, FDCAN_STBY, FDCAN_TX

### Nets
3V3: C59.1 U4.5(VIO)
5V: C45.1 U4.3(VDD)
GND: C45.2 C59.2 R20.2 U4.2(VSS) U29.3
FDCAN_RX: U4.4(RXD) ; port FDCAN_RX
FDCAN_STBY: R20.1 U4.8(STBY) ; port FDCAN_STBY
FDCAN_TX: U4.1(TXD) ; port FDCAN_TX
NetCN18_1: CN18.1 R21.1
NetCN18_2: CN18.2 CN21.2 U4.6(CANL) U29.1
NetCN21_1: CN21.1 R21.2 U4.7(CANH) U29.2

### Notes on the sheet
- FD-CAN
- LIMITATION :
  FD-CAN signals are multiplexed with STMOD+ function
  In case FD-CAN module is connected, STMOD+ must be disconnected.
  FDCAN_RX : PMOD1-NSS
  FDCAN_TX : PMOD4-SCK
  FDCAN_STBY : PMOD12-RST
- (near R20) PH8
- PA12
- PA11
- (near U29) Default setting: Open

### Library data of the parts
C45 C59 = MCD-00006: Capacitor, MLCC, 100nF, 16V, X7R, +/-10%, 0402, T=0.5mm; Manufacturer_Part_Number: CC0402KRX7R7BB104; Manufacturer: YAGEO; Part_Preference: Recommended; Partial_Alternate_Internal_Part_Number: MCD-03299; Component_Country_Of_Origin: China; ID: 2474; Order_Code_RS: 9402047; ShowFields: YES
CN18 CN21 = MCD-00032: Header, 2x1, 2,54mm, VR, TH, Height 5.84mm/2.54mm; Part_Type: Connector; Manufacturer_Part_Number: TSW-102-07-G-S; Manufacturer: SAMTEC; Alternate_Manufacturer_Part_Number: 313102S111116; Alternate_Manufacturer: JIUBABA; Part_Preference: Recommended; Component_Country_Of_Origin: China, Costa Rica, Malaysia, USA, Vietnam; ID: 2484; Order_Code_RS: 2505044; ShowFields: YES
R20 = MCD-00053: as R44 on sheet Audio_Codec
R21 = MCD-00194: Resistor,120R,0402,1%,1/16W; Manufacturer_Part_Number: RC0402FR-07120RL; Manufacturer: YAGEO; Part_Preference: Recommended; Provided_By: SUBCO; Component_Country_Of_Origin: China; ID: 2674; ShowFields: YES
U4 = MCD-00129: High-Speed CAN Flexible Data Rate Transceiver; Manufacturer: MICROCHIP; Part_Type: IC; Part_Preference: Recommended; Provided_By: SUBCO; Component_Country_Of_Origin: Unknown; ID: 2737; ShowFields: YES
U29 = MCD-01062: Automotive dual-line Transil, transient voltage suppressor (TVS) for CAN bus. Compliant with interfaces in automotive: CAN-FD, LIN, FlexRay, MOST, SENT, USB; Part_Type: Diode; Manufacturer: STMICROELECTRONICS; BMS_Part_Number: 9179023; Manufacturer_HQ_COO: EU; Part_Preference: Recommended; Provided_By: SUBCO with ST control; Component_Country_Of_Origin: China; ID: 3427; Order_Code_RS: 124-1109; ShowFields: YES

## Sheet LCD.SchDoc: LCD
size A4; Date: Not used; ApprovedBy: Not used; CheckedBy: Not used; Author: Not used; CompanyName: STMicroelectronics; DrawnBy: Not used; Engineer: Not used; Organization: Not used; Address1: Not used; Address2: Not used; Address3: Not used; Address4: Not used; DocumentNumber: Not used; Revision: Not used; SheetNumber: 10; SheetTotal: 17
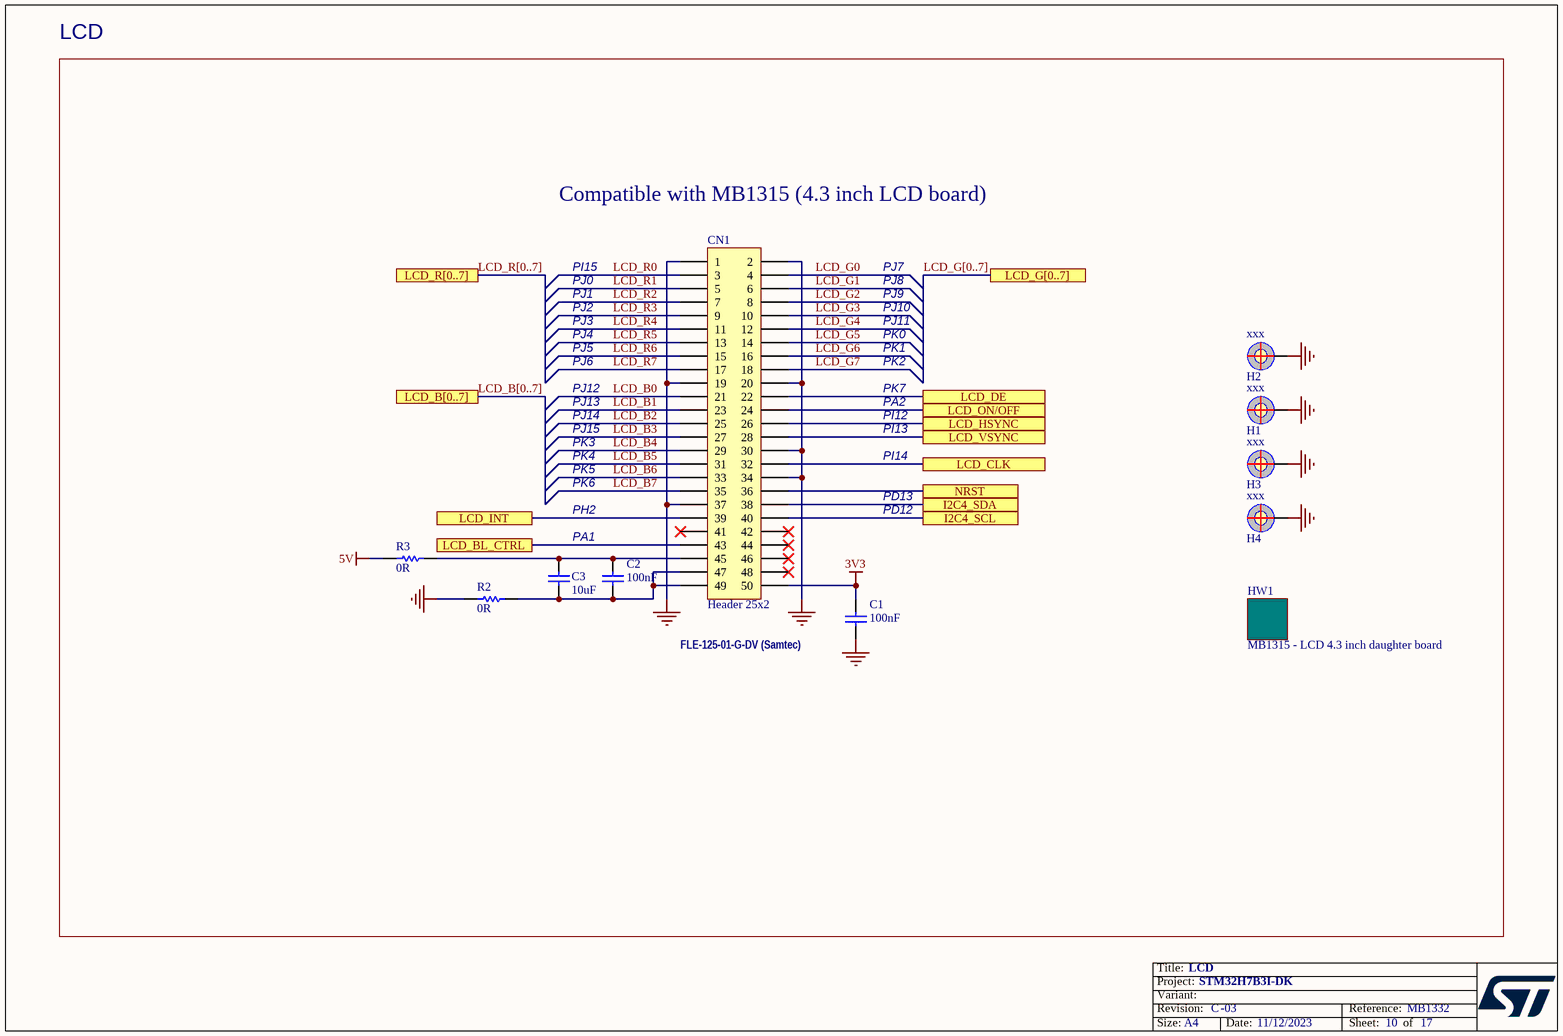
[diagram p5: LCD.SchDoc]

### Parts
C1  value 100nF  [C0402]  (hidden comment: Capacitor)
C2  value 100nF  [C0402]  (hidden comment: Capacitor)
C3  value 10uF  [C0805]  (hidden comment: Capacitor)
CN1  Header 25x2  [MOD_LCD_MB1046B__CON_SAMTEC_FLE-125-01-G-DV]
H1  value xxx  [PTH_M1261-3005-N_3P5X6_M3_H14]  (hidden comment: POSITION HOLE)  (no BOM)
H2  value xxx  [PTH_M1261-3005-N_3P5X6_M3_H14]  (hidden comment: POSITION HOLE)  (no BOM)
H3  value xxx  [PTH_M1261-3005-N_3P5X6_M3_H14]  (hidden comment: POSITION HOLE)  (no BOM)
H4  value xxx  [PTH_M1261-3005-N_3P5X6_M3_H14]  (hidden comment: POSITION HOLE)  (no BOM)
HW1  value MB1315 - LCD 4.3 inch daughter board  (hidden comment: Daughter_Board)  (no BOM)
R2  value 0R  [R0603]  (hidden comment: Resistor)
R3  value 0R  [R0603]  (hidden comment: Resistor)

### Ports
I2C4_SCL, I2C4_SDA, LCD_B[0..7], LCD_BL_CTRL, LCD_CLK, LCD_DE, LCD_G[0..7], LCD_HSYNC, LCD_INT, LCD_ON/OFF, LCD_R[0..7], LCD_VSYNC, NRST

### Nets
3V3: C1.1 CN1.50
5V: R3.1
GND: C1.2 CN1.1 CN1.2 CN1.19 CN1.20 CN1.30 CN1.34 CN1.37 H1.1 H2.1 H3.1 H4.1 R2.1
I2C4_SCL: CN1.40 ; port I2C4_SCL
I2C4_SDA: CN1.38 ; port I2C4_SDA
LCD_B0: CN1.21
LCD_B1: CN1.23
LCD_B2: CN1.25
LCD_B3: CN1.27
LCD_B4: CN1.29
LCD_B5: CN1.31
LCD_B6: CN1.33
LCD_B7: CN1.35
LCD_BL_CTRL: CN1.43 ; port LCD_BL_CTRL
LCD_CLK: CN1.32 ; port LCD_CLK
LCD_DE: CN1.22 ; port LCD_DE
LCD_G0: CN1.4
LCD_G1: CN1.6
LCD_G2: CN1.8
LCD_G3: CN1.10
LCD_G4: CN1.12
LCD_G5: CN1.14
LCD_G6: CN1.16
LCD_G7: CN1.18
LCD_HSYNC: CN1.26 ; port LCD_HSYNC
LCD_INT: CN1.39 ; port LCD_INT
LCD_ON/OFF: CN1.24 ; port LCD_ON/OFF
LCD_R0: CN1.3
LCD_R1: CN1.5
LCD_R2: CN1.7
LCD_R3: CN1.9
LCD_R4: CN1.11
LCD_R5: CN1.13
LCD_R6: CN1.15
LCD_R7: CN1.17
LCD_VSYNC: CN1.28 ; port LCD_VSYNC
T_NRST: CN1.36 ; port NRST
NetC2_1: C2.1 C3.2 CN1.45 R3.2
NetC2_2: C2.2 C3.1 CN1.47 CN1.49 R2.2

Not connected (* = marked no-connect by the designer): CN1 41* 42* 44* 46* 48*

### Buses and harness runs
bus LCD_B[0..7] = port LCD_B[0..7]
bus LCD_G[0..7] = port LCD_G[0..7]
bus LCD_R[0..7] = port LCD_R[0..7]

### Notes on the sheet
- LCD
- Compatible with MB1315 (4.3 inch LCD board)
- PI15
- PJ0
- PJ1
- PJ2
- PJ7
- PJ8
- PJ9
- PJ10
- PJ3
- PJ4
- PJ5
- PJ6
- PJ11
- PK0
- PK1
- PK2
- PJ12
- PJ13
- PJ14
- PJ15
- PK3
- PK7
- PI12
- PI13
- PA2
- PK4
- PK5
- PK6
- PH2
- PI14
- PD12
- PD13
- PA1
- (near C1) FLE-125-01-G-DV (Samtec)

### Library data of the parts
C1 C2 = MCD-00006: as C45 on sheet FDCAN
C3 = MCD-00014: Capacitor, MLCC, 10uF, 25V, X5R, 10%, 0805, T=0,85mm; Manufacturer_Part_Number: CC0805KRX5R8BB106; Manufacturer: YAGEO; Full_Alternate_Internal_Part_Number: MCD-02385; Part_Preference: Recommended; Partial_Alternate_Internal_Part_Number: MCD-03053; Provided_By: SUBCO; Component_Country_Of_Origin: China; ID: 2468; ShowFields: YES
CN1 = MCD-01222: Header 25x2 for MB1046 - LCD 4.3 inches daughter board; Part_Type: Connector; Manufacturer_Part_Number: FLE-125-01-G-DV; Manufacturer: SAMTEC; Alternate_Manufacturer_Part_Number: 234250M1410; Alternate_Manufacturer: JIUBABA; Part_Preference: Recommended; Partial_Alternate_Internal_Part_Number: MCD-03153; Provided_By: SUBCO; Component_Country_Of_Origin: China, Costa Rica, Malaysia, USA, Vietnam; ID: 3274; Order_Code_RS: 766-8965; ShowFields: YES
H1-H4 = MCD-00035: POSITION HOLE C6D3R5; Part_Type: Misc; Part_Preference: Recommended; Component_Country_Of_Origin: Unknown; ID: 2482; ShowFields: YES
HW1 = MCD-01956: MB1315 - LCD 4.3 inch daughter board; Part_Type: Display; Manufacturer_Part_Number: MB1315 - LCD 4.3 inches daughter board; Manufacturer: STMICROELECTRONICS; Manufacturer_HQ_COO: EU; Part_Preference: Recommended; Provided_By: SUBCO with ST control; Component_Country_Of_Origin: Unknown; ID: 4056; ShowFields: YES
R2 R3 = MCD-00056: Resistor,0R,0603,5%,1/10W; Manufacturer_Part_Number: RC0603JR-070RL; Manufacturer: YAGEO; Part_Preference: Recommended; Provided_By: SUBCO; Component_Country_Of_Origin: China; ID: 2536; Order_Code_RS: 9233130RL; ShowFields: YES

## Sheet Memory.SchDoc: Memory
size A4; Date: Not used; ApprovedBy: Not used; CheckedBy: Not used; Author: Not used; CompanyName: STMicroelectronics; DrawnBy: Not used; Engineer: Not used; Organization: Not used; Address1: Not used; Address2: Not used; Address3: Not used; Address4: Not used; DocumentNumber: Not used; Revision: Not used; SheetNumber: 5; SheetTotal: 17
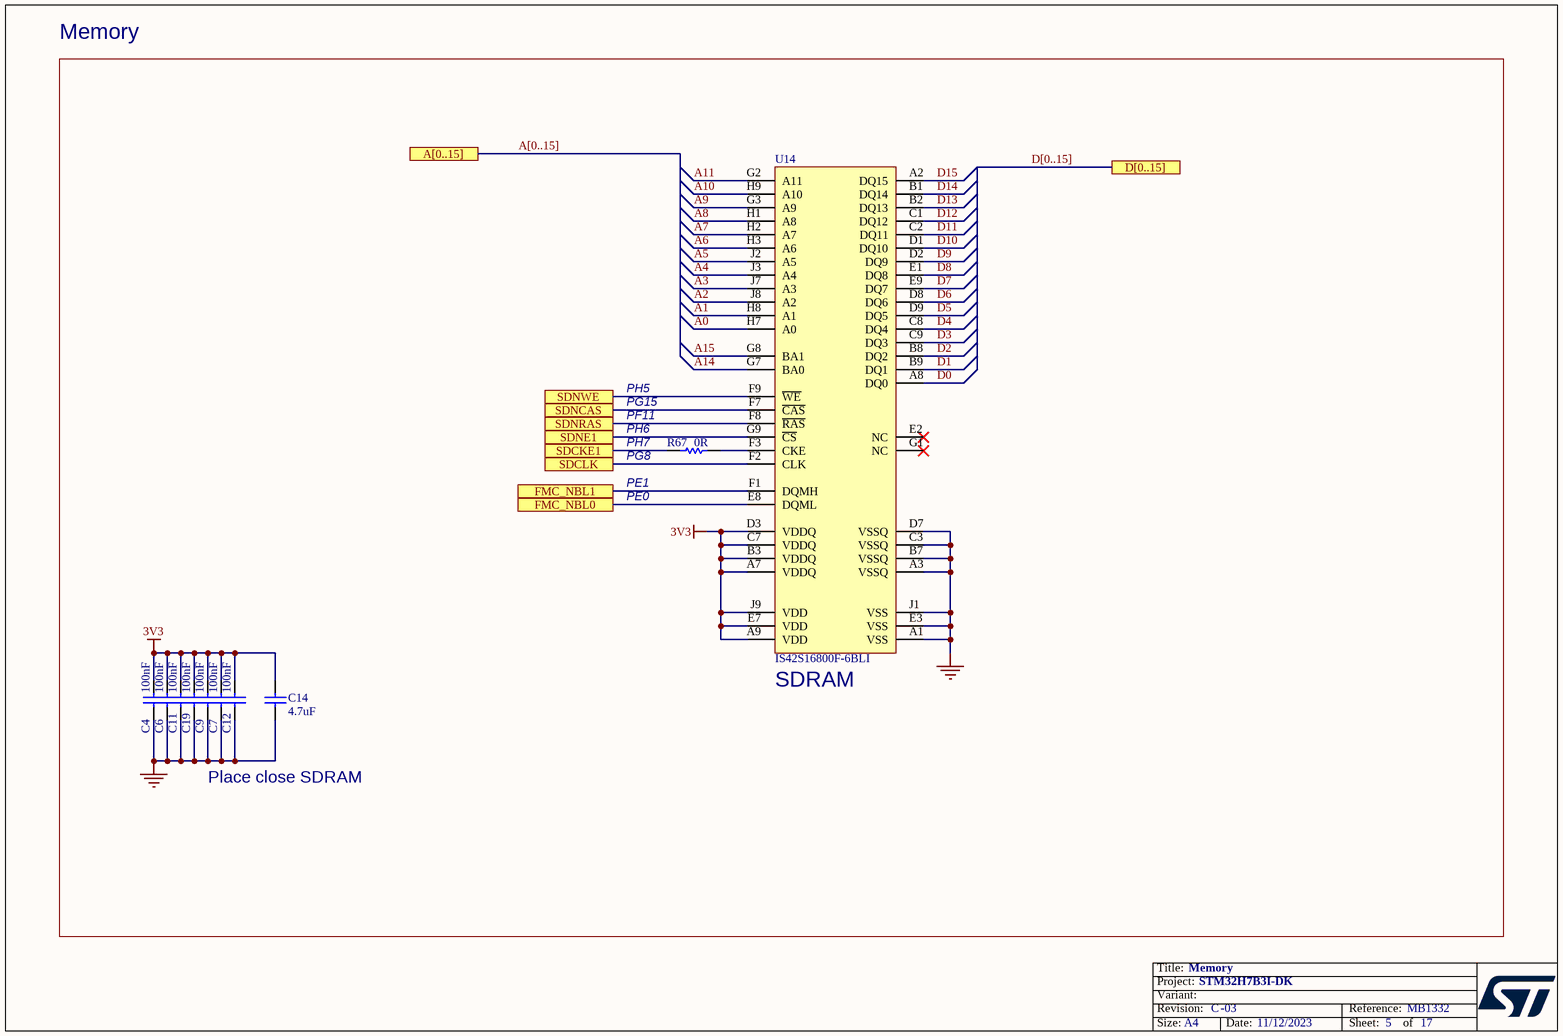
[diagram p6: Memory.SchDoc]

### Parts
C4  value 100nF  [C0402]  (hidden comment: Capacitor)
C6  value 100nF  [C0402]  (hidden comment: Capacitor)
C7  value 100nF  [C0402]  (hidden comment: Capacitor)
C9  value 100nF  [C0402]  (hidden comment: Capacitor)
C11  value 100nF  [C0402]  (hidden comment: Capacitor)
C12  value 100nF  [C0402]  (hidden comment: Capacitor)
C14  value 4.7uF  [C0603_H0P8]  (hidden comment: Capacitor)
C19  value 100nF  [C0402]  (hidden comment: Capacitor)
R67  value 0R  [R0603]  (hidden comment: Resistor)
U14  IS42S16800F-6BLI  [ICC_TFBGA54_3X9-BALL-X2_8X8_P080]

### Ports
A[0..15], D[0..15], FMC_NBL0, FMC_NBL1, SDCKE1, SDCLK, SDNCAS, SDNE1, SDNRAS, SDNWE

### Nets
3V3: C4.1 C6.1 C7.1 C9.1 C11.1 C12.1 C14.2 C19.1 U14.A7(VDDQ) U14.A9(VDD) U14.B3(VDDQ) U14.C7(VDDQ) U14.D3(VDDQ) U14.E7(VDD) U14.J9(VDD)
GND: C4.2 C6.2 C7.2 C9.2 C11.2 C12.2 C14.1 C19.2 U14.A1(VSS) U14.A3(VSSQ) U14.B7(VSSQ) U14.C3(VSSQ) U14.D7(VSSQ) U14.E3(VSS) U14.J1(VSS)
A0: U14.H7(A0)
A1: U14.H8(A1)
A2: U14.J8(A2)
A3: U14.J7(A3)
A4: U14.J3(A4)
A5: U14.J2(A5)
A6: U14.H3(A6)
A7: U14.H2(A7)
A8: U14.H1(A8)
A9: U14.G3(A9)
A10: U14.H9(A10)
A11: U14.G2(A11)
A14: U14.G7(BA0)
A15: U14.G8(BA1)
D0: U14.A8(DQ0)
D1: U14.B9(DQ1)
D2: U14.B8(DQ2)
D3: U14.C9(DQ3)
D4: U14.C8(DQ4)
D5: U14.D9(DQ5)
D6: U14.D8(DQ6)
D7: U14.E9(DQ7)
D8: U14.E1(DQ8)
D9: U14.D2(DQ9)
D10: U14.D1(DQ10)
D11: U14.C2(DQ11)
D12: U14.C1(DQ12)
D13: U14.B2(DQ13)
D14: U14.B1(DQ14)
D15: U14.A2(DQ15)
FMC_NBL0: U14.E8(DQML) ; port FMC_NBL0
FMC_NBL1: U14.F1(DQMH) ; port FMC_NBL1
SDCKE1: R67.2 ; port SDCKE1
SDCLK: U14.F2(CLK) ; port SDCLK
SDNCAS: U14.F7(~{CAS}) ; port SDNCAS
SDNE1: U14.G9(~{CS}) ; port SDNE1
SDNRAS: U14.F8(~{RAS}) ; port SDNRAS
SDNWE: U14.F9(~{WE}) ; port SDNWE
NetR67_1: R67.1 U14.F3(CKE)

Not connected (* = marked no-connect by the designer): U14 E2(NC)* G1(NC)*

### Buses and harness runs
bus A[0..15] = port A[0..15]
bus D[0..15] = port D[0..15]

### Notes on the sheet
- Memory
- PH5
- (near R67) PG15
- (near R67) PF11
- (near R67) PH6
- (near R67) PH7
- (near R67) PG8
- (near R67) PE1
- PE0
- (near U14) SDRAM
- Place close SDRAM

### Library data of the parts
C4 C6 C7 C9 C11 C12 C19 = MCD-00006: as C45 on sheet FDCAN
C14 = MCD-01721: Capacitor, 4.7uF, 10V, X5R, 10%, 0603, T=0.8mm; Manufacturer_Part_Number: CC0603KRX5R6BB475; Manufacturer: YAGEO; Part_Preference: Recommended; Provided_By: SUBCO; Component_Country_Of_Origin: China; ID: 3821; ShowFields: YES
R67 = MCD-00056: as R2 on sheet LCD
U14 = MCD-01143: SDRAM 128Mbits - 166MHz - 54-ball BGA - x16 - 3.3V; Part_Type: IC; Manufacturer: ISSI; Part_Preference: Recommended; Provided_By: SUBCO; Component_Country_Of_Origin: Taiwan; ID: 3352; ShowFields: YES

## Sheet OCSPI.SchDoc: OCSPI
size A4; Date: Not used; ApprovedBy: Not used; CheckedBy: Not used; Author: Not used; CompanyName: STMicroelectronics; DrawnBy: Not used; Engineer: Not used; Organization: Not used; Address1: Not used; Address2: Not used; Address3: Not used; Address4: Not used; DocumentNumber: Not used; Revision: Not used; SheetNumber: 6; SheetTotal: 17
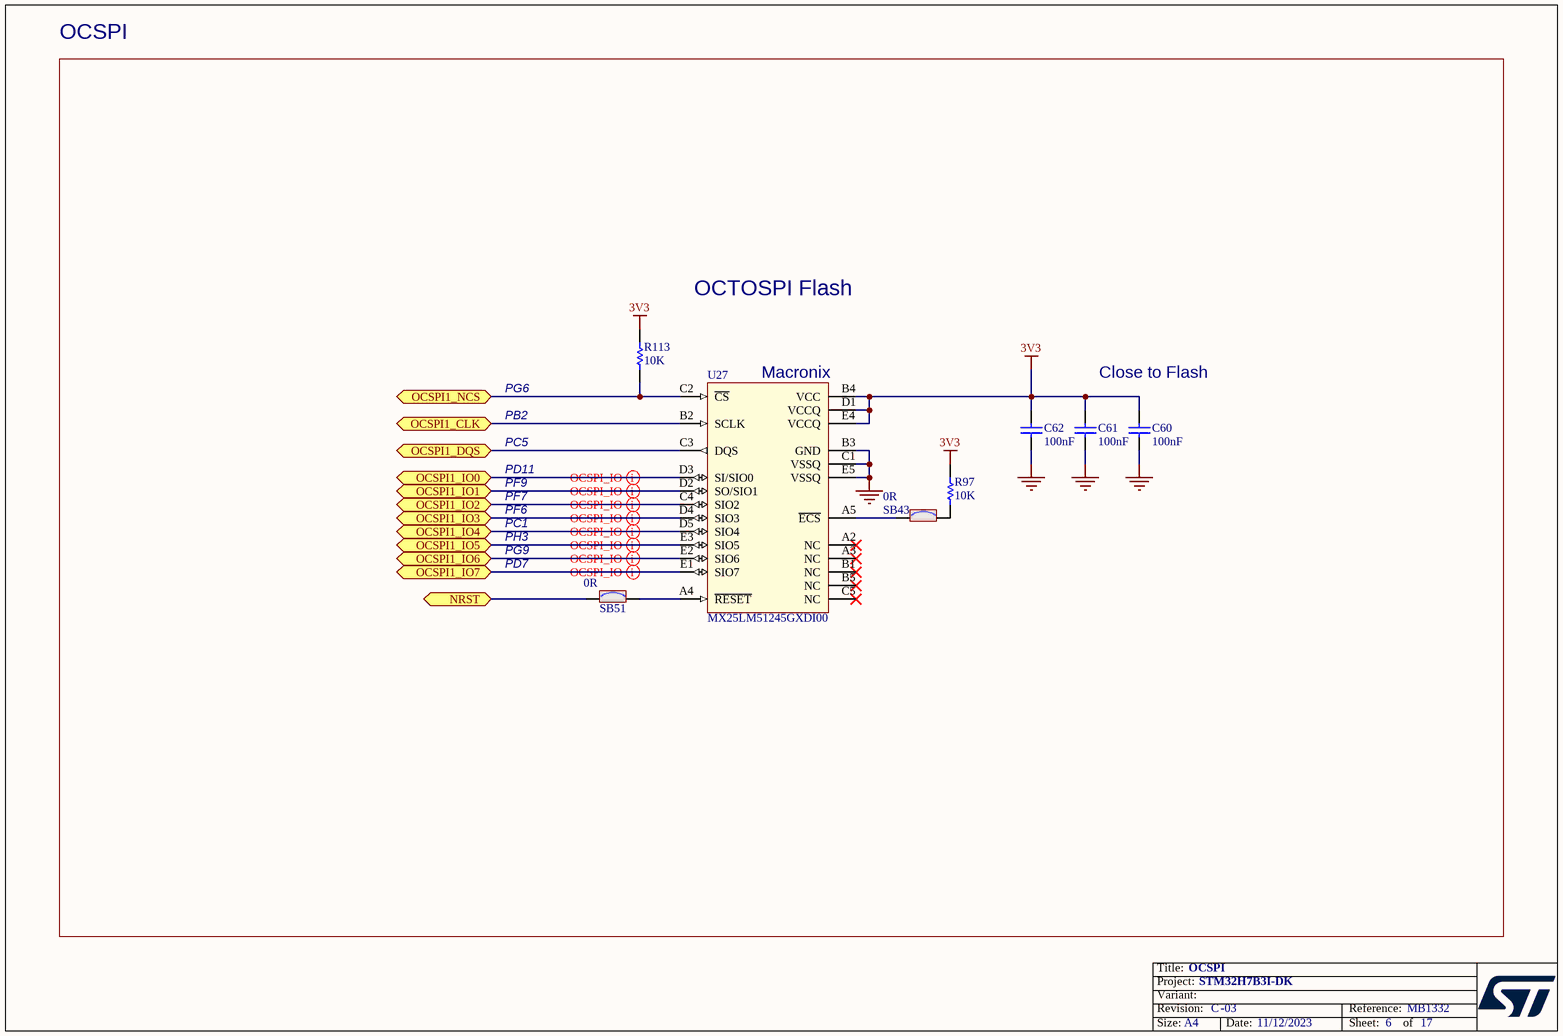
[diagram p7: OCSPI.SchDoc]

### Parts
C60  value 100nF  [C0402]  (hidden comment: Capacitor)
C61  value 100nF  [C0402]  (hidden comment: Capacitor)
C62  value 100nF  [C0402]  (hidden comment: Capacitor)
R97  value 10K  [R0402]  (hidden comment: Resistor)
R113  value 10K  [R0402]  (hidden comment: Resistor)
SB43  value 0R  [SOLDER-BRIDGE_R0603-0R]  (hidden comment: SB_ON)
SB51  value 0R  [SOLDER-BRIDGE_R0603-0R]  (hidden comment: SB_ON)
U27  MX25LM51245GXDI00  [ICC_BGA24_5X5-BALL-ARRAY_6X8_P1]

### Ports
NRST (bidir), OCSPI1_CLK (bidir), OCSPI1_DQS (bidir), OCSPI1_IO0 (bidir), OCSPI1_IO1 (bidir), OCSPI1_IO2 (bidir), OCSPI1_IO3 (bidir), OCSPI1_IO4 (bidir), OCSPI1_IO5 (bidir), OCSPI1_IO6 (bidir), OCSPI1_IO7 (bidir), OCSPI1_NCS (bidir)

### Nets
3V3: C60.2 C61.2 C62.2 R97.2 R113.1 U27.B4(VCC) U27.D1(VCCQ) U27.E4(VCCQ)
GND: C60.1 C61.1 C62.1 U27.B3(GND) U27.C1(VSSQ) U27.E5(VSSQ)
OCSPI1_CLK: U27.B2(SCLK) ; port OCSPI1_CLK
OCSPI1_DQS: U27.C3(DQS) ; port OCSPI1_DQS
OCSPI1_IO0: U27.D3(SI/SIO0) ; port OCSPI1_IO0
OCSPI1_IO1: U27.D2(SO/SIO1) ; port OCSPI1_IO1
OCSPI1_IO2: U27.C4(SIO2) ; port OCSPI1_IO2
OCSPI1_IO3: U27.D4(SIO3) ; port OCSPI1_IO3
OCSPI1_IO4: U27.D5(SIO4) ; port OCSPI1_IO4
OCSPI1_IO5: U27.E3(SIO5) ; port OCSPI1_IO5
OCSPI1_IO6: U27.E2(SIO6) ; port OCSPI1_IO6
OCSPI1_IO7: U27.E1(SIO7) ; port OCSPI1_IO7
OCSPI1_NCS: R113.2 U27.C2(~{CS}) ; port OCSPI1_NCS
T_NRST: SB51.1 ; port NRST
NetR97_1: R97.1 SB43.2
NetSB43_1: SB43.1 U27.A5(~{ECS})
NetSB51_2: SB51.2 U27.A4(~{RESET})

Not connected (* = marked no-connect by the designer): U27 A2(NC)* A3(NC)* B1(NC)* B5(NC)* C5(NC)*

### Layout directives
rule Undefined; rule ? ; rule ? : OCSPI1_IO0, OCSPI1_IO1, OCSPI1_IO2, OCSPI1_IO3, OCSPI1_IO4, OCSPI1_IO5, OCSPI1_IO6, OCSPI1_IO7

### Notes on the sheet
- OCSPI
- OCTOSPI Flash
- (near U27) Macronix
- Close to Flash
- PG6
- PB2
- PC5
- PD11
- PF6
- PF7
- PF9
- PH3
- PC1
- PG9
- PD7

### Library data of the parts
C60-C62 = MCD-00006: as C72 on sheet Audio_Codec
R97 R113 = MCD-00053: as R44 on sheet Audio_Codec
SB43 SB51 = MCD-00071: as SB20 on sheet Audio_Codec
U27 = MCD-00246: Memory,Octo-SPI-NOR,512Mb,2048x16,133MHz,3V,DTR,BGA24, CMOS MXSMIO; Part_Type: IC; Manufacturer: MACRONIX; Part_Preference: Recommended; ECCN_US: 3A991.b.1.a; Provided_By: SUBCO; Component_Country_Of_Origin: Unknown; ID: 2623; ShowFields: YES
